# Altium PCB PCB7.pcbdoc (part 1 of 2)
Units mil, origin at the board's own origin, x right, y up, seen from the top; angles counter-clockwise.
Board outline 2240.69 x 1522.77 mil, 8 copper layers (Top Layer, Inner1, Inner2, Inner3, Inner4, Inner5, Inner6, Bottom Layer); 54 components, 78 nets, 968 pads, 282 vias.
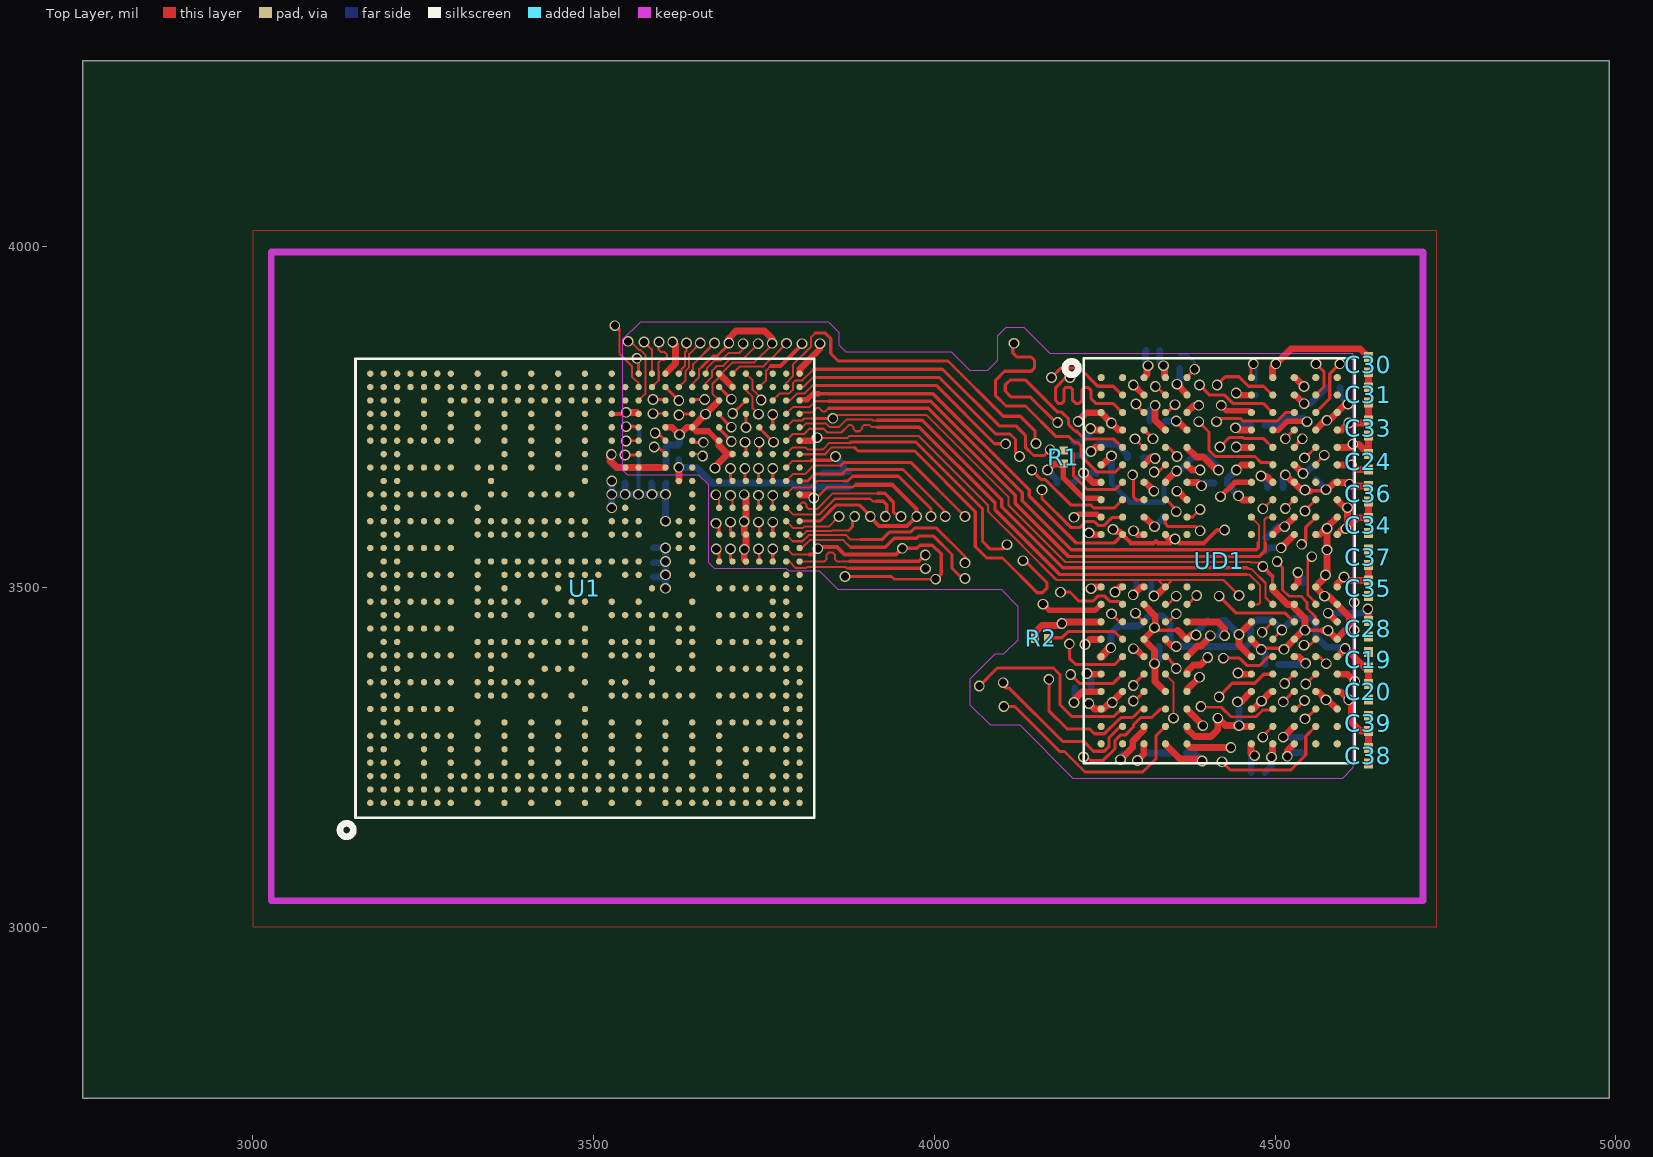
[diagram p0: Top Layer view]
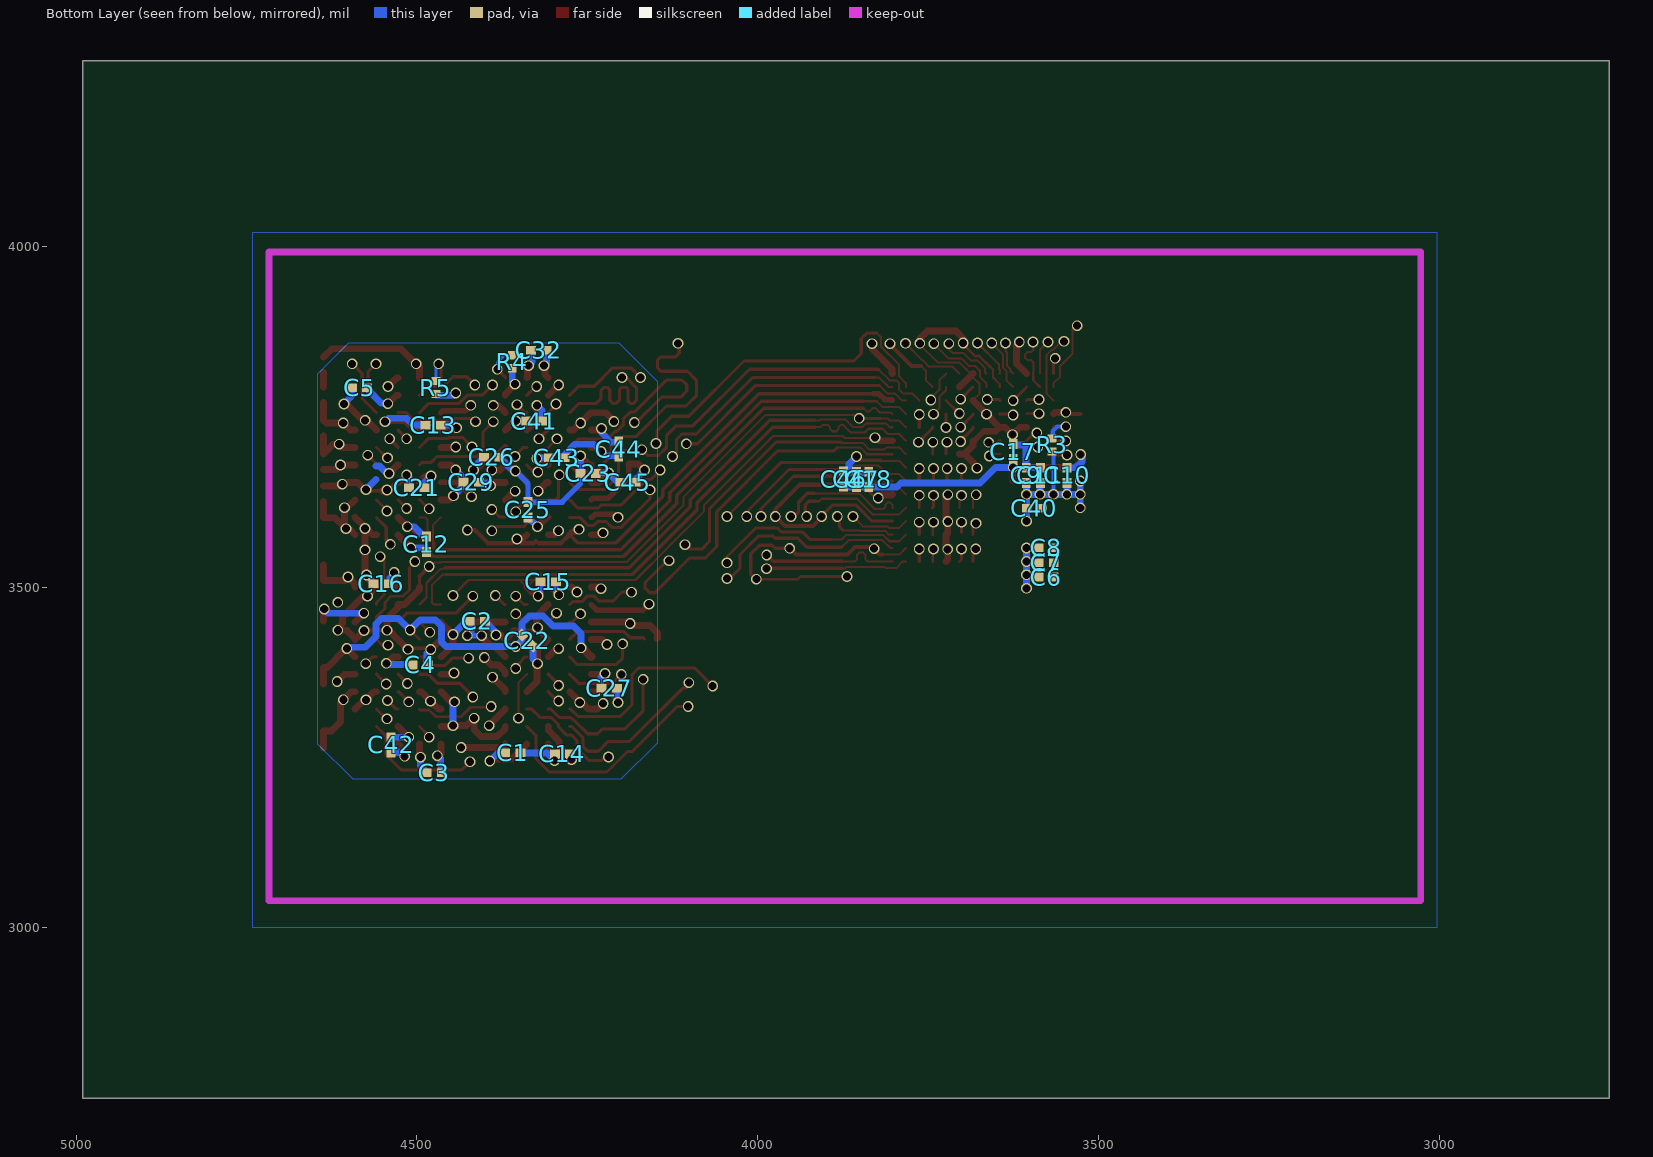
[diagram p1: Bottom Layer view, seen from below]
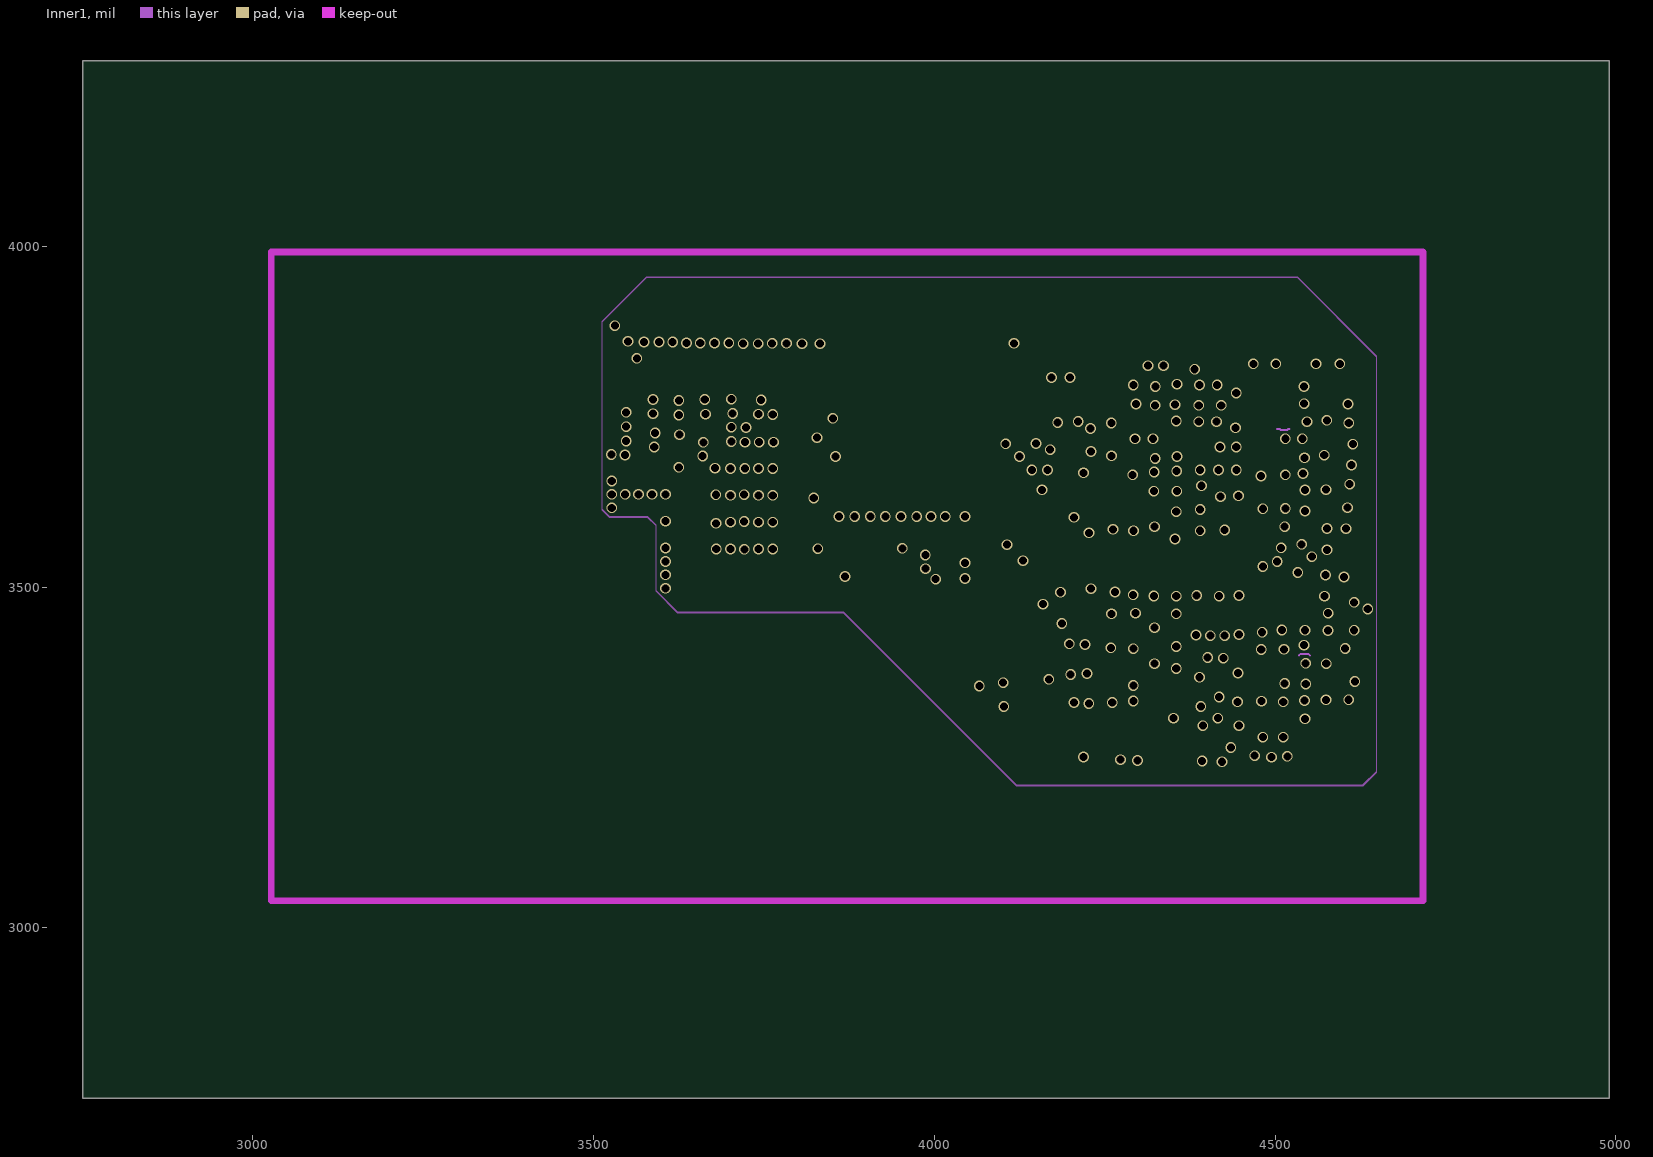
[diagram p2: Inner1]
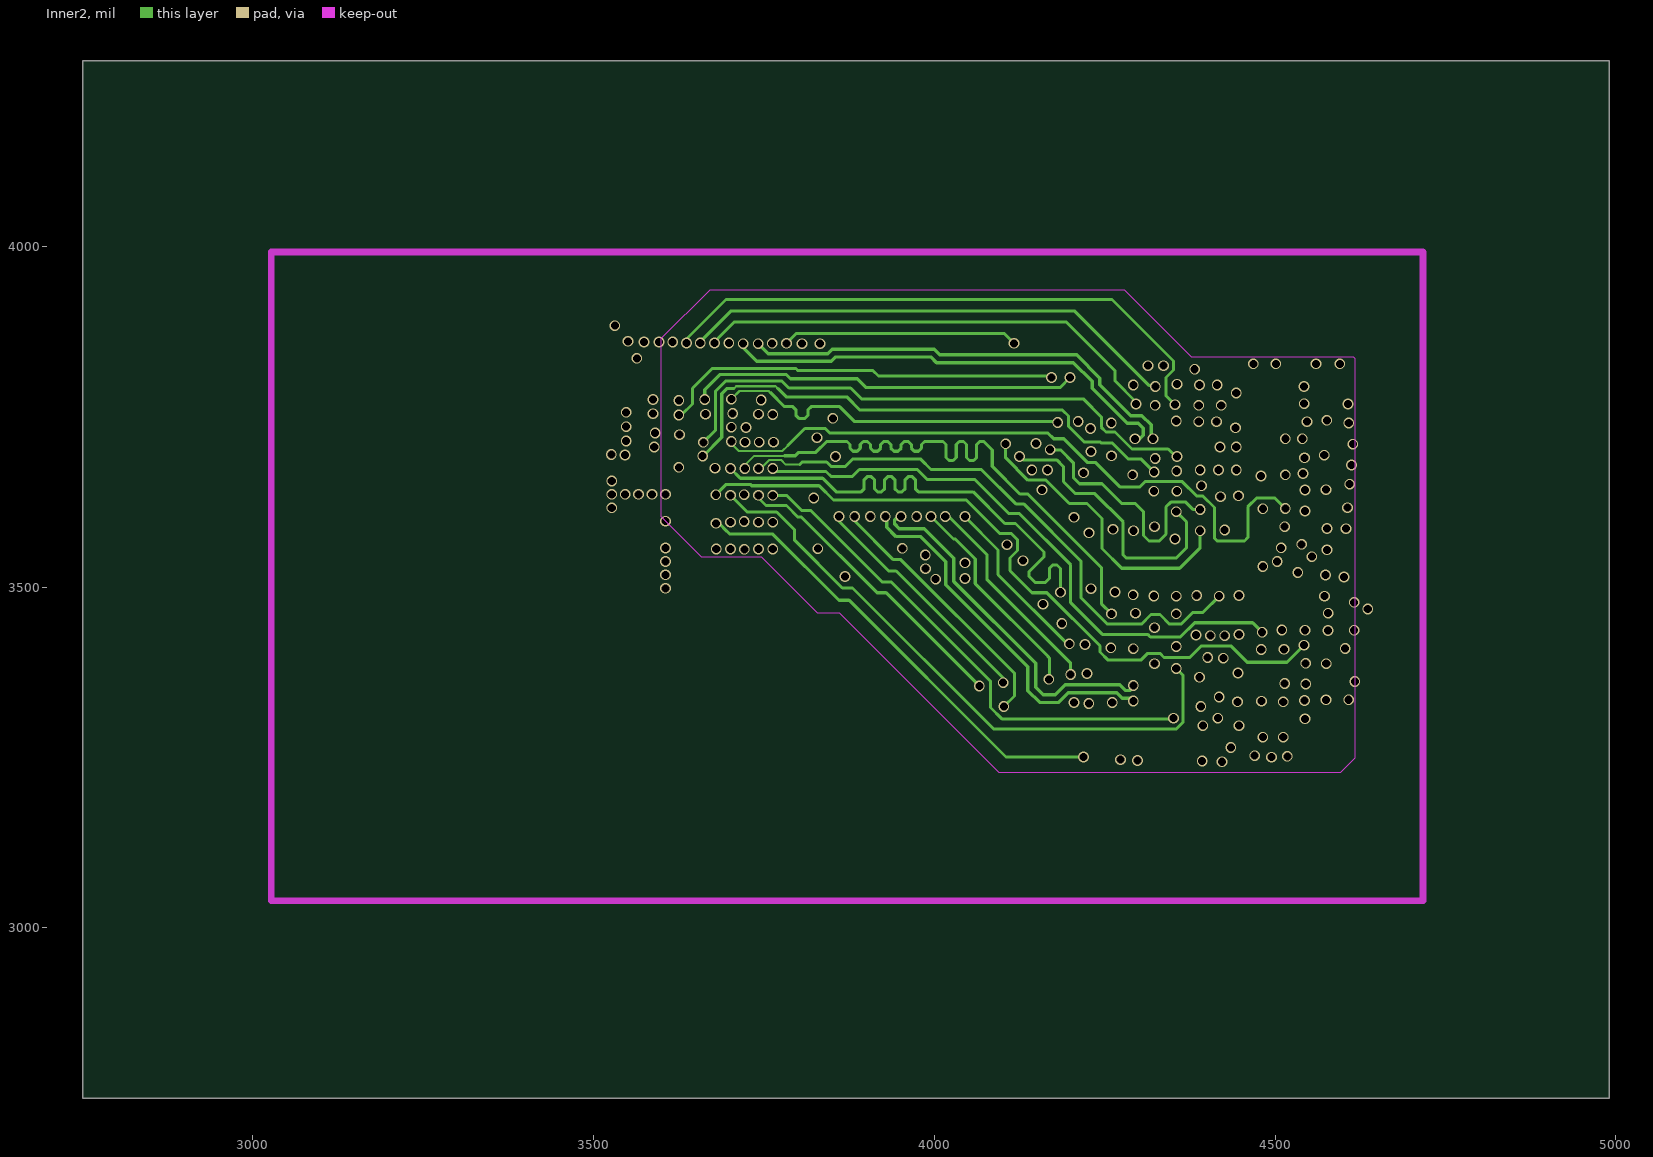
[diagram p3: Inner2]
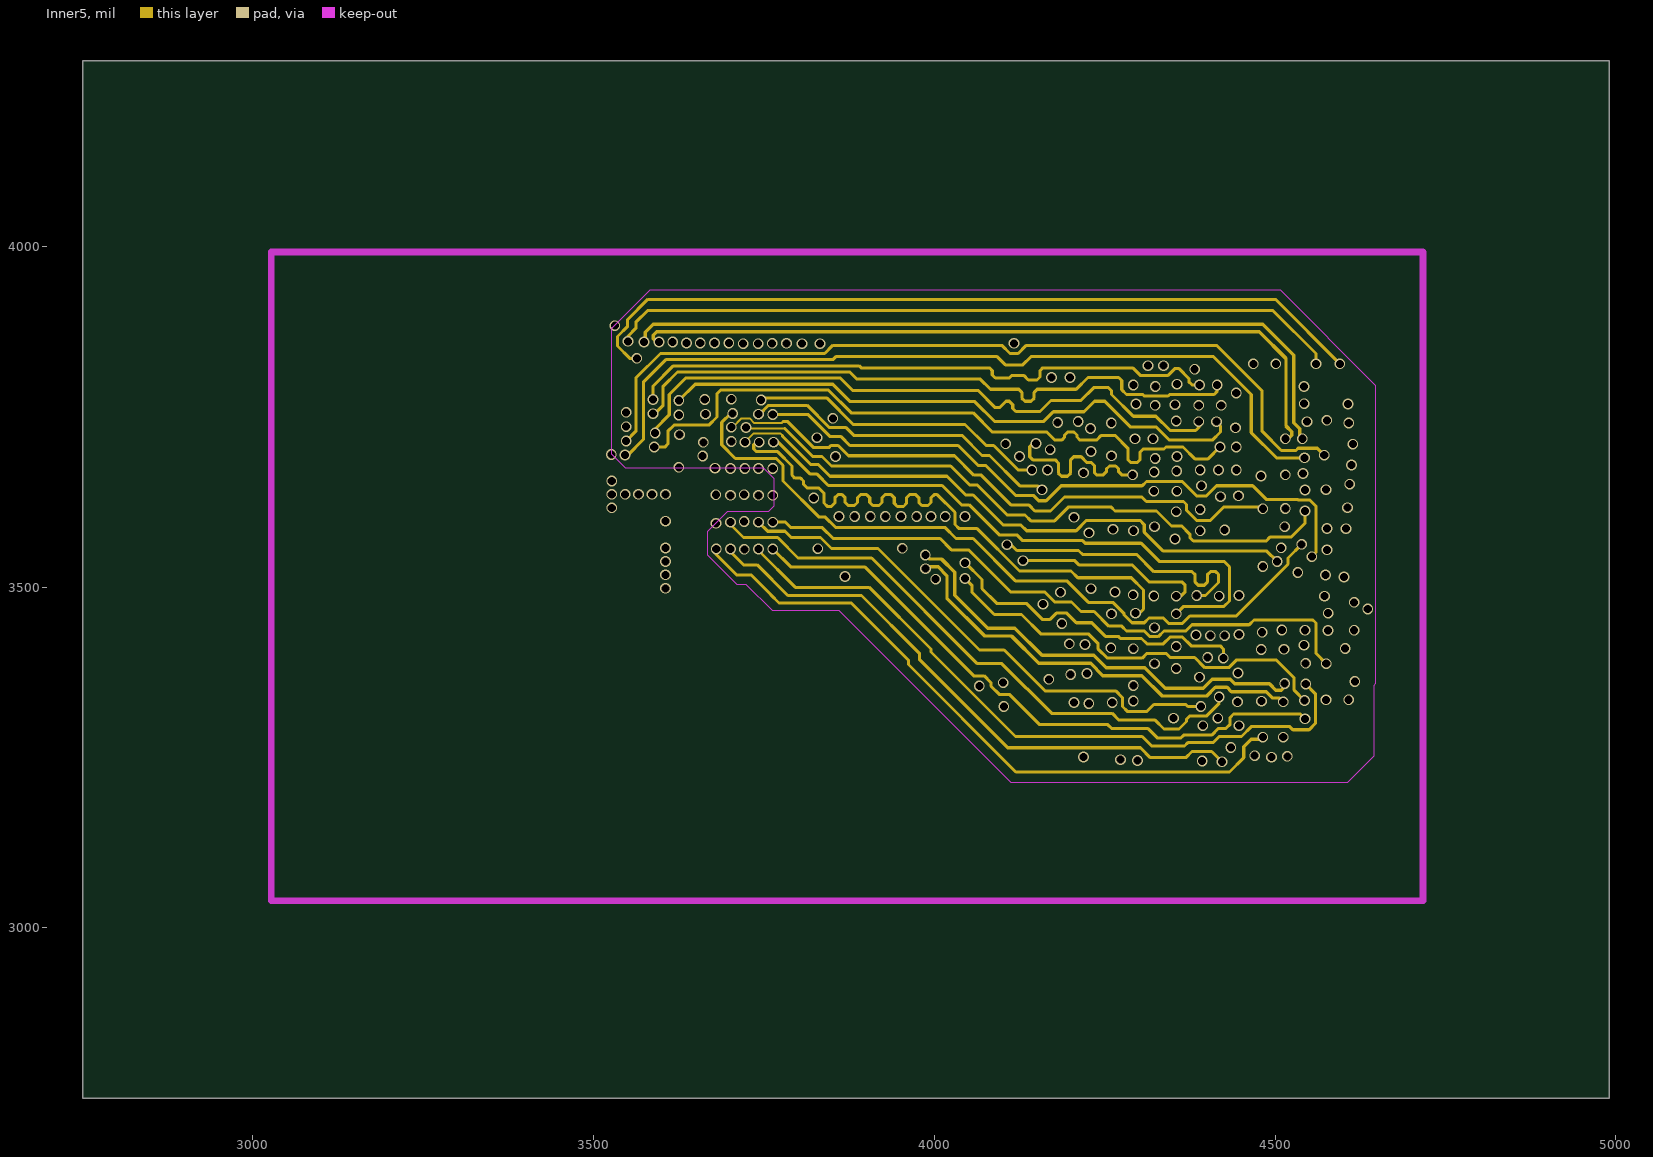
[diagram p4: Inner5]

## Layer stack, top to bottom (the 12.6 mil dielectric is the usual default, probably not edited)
Top Layer: signal copper (thickness not stored)
Dielectric: dielectric 12.6, FR-4, Dk 4.8
Inner1: signal copper (thickness not stored)
Dielectric: dielectric 12.6, FR-4, Dk 4.8
Inner2: signal copper (thickness not stored)
Dielectric: dielectric 12.6, FR-4, Dk 4.8
Inner3: signal copper (thickness not stored)
Dielectric: dielectric 12.6, FR-4, Dk 4.8
Inner4: signal copper (thickness not stored)
Dielectric: dielectric 12.6, FR-4, Dk 4.8
Inner5: signal copper (thickness not stored)
Dielectric: dielectric 12.6, FR-4, Dk 4.8
Inner6: signal copper (thickness not stored)
Dielectric: dielectric 12.6, FR-4, Dk 4.8
Bottom Layer: signal copper (thickness not stored)

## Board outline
4990.69,2750 2750,2750 2750,4272.77 4990.69,4272.77

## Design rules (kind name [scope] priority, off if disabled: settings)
Clearance safeClearance [All] p1: gap=7 ignorepadtopadclearanceinfootprint=FALSE except(3: Track-Track Track-SMDPad SMDPad-SMDPad Track-THPad SMDPad-THPad THPad-THPad Track-Via SMDPad-Via THPad-Via Via-Via Track-Hole SMDPad-Hole THPad-Hole Via-Hole; 3.5: Track-Fill SMDPad-Fill THPad-Fill Via-Fill Fill-Fill Track-Region SMDPad-Region THPad-Region Via-Region Fill-Region Region-Region Track-Poly SMDPad-Poly THPad-Poly Via-Poly Fill-Poly Region-Poly Poly-Poly Track-Text SMDPad-Text THPad-Text Via-Text Fill-Text Region-Text Poly-Text Text-Text SMDPad-Sheet THPad-Sheet Fill-Hole Region-Hole Poly-Hole Text-Hole Sheet-Hole; 11.8: Track-Sheet Via-Sheet Fill-Sheet Region-Sheet Poly-Sheet Text-Sheet)
DiffPairsRouting differentialPair [All] p1: maxuncoupledlength=50 minlimit=0 maxlimit=4.0157 mostfreqgap=4.0157 toplayer_minwidth=4.0157 toplayer_prefwidth=10 toplayer_maxwidth=100 bottomlayer_minwidth=4.0157 bottomlayer_prefwidth=10 bottomlayer_maxwidth=100 midlayer1_minwidth=4.0157 midlayer1_prefwidth=10 midlayer1_maxwidth=100 midlayer2_minwidth=4.0157 midlayer2_prefwidth=10 midlayer2_maxwidth=100 midlayer3_minwidth=4.0157 midlayer3_prefwidth=10 midlayer3_maxwidth=100 midlayer4_minwidth=4.0157 midlayer4_prefwidth=10 midlayer4_maxwidth=100 midlayer5_minwidth=4.0157 midlayer5_prefwidth=10 midlayer5_maxwidth=100 midlayer6_minwidth=4.0157 midlayer6_prefwidth=10 midlayer6_maxwidth=100
PasteMaskExpansion pasteMaskExpansion [All] p1: expansion=0
PlaneConnect innerPlane [All] p1: planeconnectstyle=Relief reliefexpansion=20 reliefentries=4 reliefconductorwidth=10 reliefairgap=10
PolygonConnect copperRegion [All] p1: connectstyle=Relief reliefentries=4 reliefconductorwidth=10 polygonreliefangle="90 Angle" airgapwidth=10
PolygonConnect TBCopper [All] p1: connectstyle=Relief reliefentries=4 reliefconductorwidth=5.9843 polygonreliefangle="90 Angle" airgapwidth=5.9843
PolygonConnect DRAMCopper [All] p1: connectstyle=Relief reliefentries=4 reliefconductorwidth=4.0157 polygonreliefangle="90 Angle" airgapwidth=4.0157
RoutingVias viaSize [All] p1: viastyle="Through Hole" holewidth=7.9134 minholewidth=7.9134 maxholewidth=236.1812 width=17.7166 minwidth=15.748 maxwidth=393.7008
SolderMaskExpansion solderMaskExpansion [All] p1: useseparateexpansions=TRUE expansion=4.0157 expansionbottom=4.0157
Width trackWidth [All] p1: maxlimit=100 minlimit=3 preferedwidth=4

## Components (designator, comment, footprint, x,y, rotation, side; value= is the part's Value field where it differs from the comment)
C1 "0201X225M6R3NT" "c0201 nsk" 4359,3256.77 r180 bottom
C2 "0201X225M6R3NT" "c0201 nsk" 4411,3449.77 r180 bottom
C3 "GRM033R61A104KE15D" "c0201 nsk" 4475,3227.77 r0 bottom
C4 "GRM033R61A104KE15D" "c0201 nsk" 4495.5,3385.77 r0 bottom
C5 "GRM033R61A104KE15D" "c0201 nsk" 4584,3792.77 r180 bottom
C6 "GRM033R61A104KE15D" "c0201 nsk" 3577,3514.77 r0 bottom
C7 "GRM033R61A104KE15D" "c0201 nsk" 3577,3535.77 r0 bottom
C8 "GRM033R61A104KE15D" "c0201 nsk" 3577,3557.77 r0 bottom
C9 "GRM033R61A104KE15D" "c0201 nsk" 3606,3663.77 r270 bottom
C10 "GRM033R61A104KE15D" "c0201 nsk" 3546,3663.77 r270 bottom
C11 "GRM033R61A104KE15D" "c0201 nsk" 3585,3663.77 r270 bottom
C12 "GRM033R61A104KE15D" "c0201 nsk" 4486,3562.77 r270 bottom
C13 "GRM033R61A104KE15D" "c0201 nsk" 4476,3737.77 r180 bottom
C14 "GRM033R61A104KE15D" "c0201 nsk" 4286.13,3255.54 r180 bottom
C15 "GRM033R61A104KE15D" "c0201 nsk" 4307,3507.77 r180 bottom
C16 "GRM033R61A104KE15D" "c0201 nsk" 4552,3504.77 r180 bottom
C17 "0201X225M6R3NT" "c0201 nsk" 3625,3699.27 r90 bottom
C18 "GRM033R61A104KE15D" "c0201 nsk" 3837,3657.77 r270 bottom
C19 "0201X225M6R3NT" "c0201 nsk" 4637,3393.77 r90 top
C20 "GRM033R61A104KE15D" "c0201 nsk" 4637,3346.77 r90 top
C21 "GRM033R61A104KE15D" "c0201 nsk" 4500,3645.77 r180 bottom
C22 "GRM033R61A104KE15D" "c0201 nsk" 4338,3421.77 r45 bottom
C23 "GRM033R61A104KE15D" "c0201 nsk" 4249,3666.77 r0 bottom
C24 "GRM033R61A104KE15D" "c0201 nsk" 4637,3683.77 r270 top
C25 "GRM033R61A104KE15D" "c0201 nsk" 4337,3613.77 r90 bottom
C26 "GRM033R61A104KE15D" "c0201 nsk" 4390,3690.77 r180 bottom
C27 "0201X225M6R3NT" "c0201 nsk" 4218,3351.77 r0 bottom
C28 "0201X225M6R3NT" "c0201 nsk" 4637,3438.77 r270 top
C29 "GRM033R61A104KE15D" "c0201 nsk" 4420.5,3653.77 r0 bottom
C30 "GRM033R61A104KE15D" "c0201 nsk" 4637,3826.77 r90 top
C31 "GRM033R61A104KE15D" "c0201 nsk" 4637,3781.77 r270 top
C32 "0201X225M6R3NT" "c0201 nsk" 4321,3847.77 r180 bottom
C33 "GRM033R61A104KE15D" "c0201 nsk" 4637,3733.77 r90 top
C34 "GRM033R61A104KE15D" "c0201 nsk" 4637,3590.77 r90 top
C35 "GRM033R61A104KE15D" "c0201 nsk" 4637,3498.77 r90 top
C36 "GRM033R61A104KE15D" "c0201 nsk" 4637,3636.77 r270 top
C37 "GRM033R61A104KE15D" "c0201 nsk" 4637,3543.77 r270 top
C38 "GRM033R61A104KE15D" "c0201 nsk" 4637,3252.77 r90 top
C39 "GRM033R61A104KE15D" "c0201 nsk" 4637,3299.77 r270 top
C40 "GRM033R61A104KE15D" "c0201 nsk" 3594,3615.77 r0 bottom
C41 "GRM033R61A104KE15D" "c0201 nsk" 4328,3743.77 r0 bottom
C42 "GRM033R61A104KE15D" "c0201 nsk" 4538,3268.77 r90 bottom
C43 "GRM033R61A104KE15D" "c0201 nsk" 4295,3689.77 r0 bottom
C44 "GRM033R61A104KE15D" "c0201 nsk" 4204,3702.77 r90 bottom
C45 "GRM033R61A104KE15D" "c0201 nsk" 4190,3653.77 r180 bottom
C46 "0201X225M6R3NT" "c0201 nsk" 3874,3658.77 r90 bottom
C47 "GRM033R61A104KE15D" "c0201 nsk" 3855,3657.77 r270 bottom
R1 "Res_0201" "r0201 nsk" 4190,3690.77 r270 top
R2 "Res_0201" "r0201 nsk" 4157,3424.77 r180 top
R3 "Res_0201" "r0201 nsk" 3568,3708.77 r270 bottom
R4 "Res_0201" "r0201 nsk" 4360,3830.77 r270 bottom
R5 "Res_0201" "r0201 nsk" 4472,3792.77 r270 bottom
U1 "T527" T527-BGA664 3487.26,3498.32 r90 top
UD1 "LPDDR4_FBGA200" BGA200P65_80B1000_1500H90 4418,3538.77 r0 top

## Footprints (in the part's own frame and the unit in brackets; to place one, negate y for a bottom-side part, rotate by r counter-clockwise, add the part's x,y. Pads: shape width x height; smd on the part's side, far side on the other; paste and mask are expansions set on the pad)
BGA200P65_80B1000_1500H90 [mm]
  round 0.27 smd: A1(-4.4,6.825) A2(-3.6,6.825) A3(-2.8,6.825) A4(-2,6.825) A5(-1.2,6.825) A8(1.2,6.825) A9(2,6.825) A10(2.8,6.825) A11(3.6,6.825) A12(4.4,6.825) AA1(-4.4,-6.175) AA2(-3.6,-6.175) AA3(-2.8,-6.175) AA4(-2,-6.175) AA5(-1.2,-6.175) AA8(1.2,-6.175) AA9(2,-6.175) AA10(2.8,-6.175) AA11(3.6,-6.175) AA12(4.4,-6.175) AB1(-4.4,-6.825) AB2(-3.6,-6.825) AB3(-2.8,-6.825) AB4(-2,-6.825) AB5(-1.2,-6.825) AB8(1.2,-6.825) AB9(2,-6.825) AB10(2.8,-6.825) AB11(3.6,-6.825) AB12(4.4,-6.825) B1(-4.4,6.175) B2(-3.6,6.175) B3(-2.8,6.175) B4(-2,6.175) B5(-1.2,6.175) B8(1.2,6.175) B9(2,6.175) B10(2.8,6.175) B11(3.6,6.175) B12(4.4,6.175) C1(-4.4,5.525) C2(-3.6,5.525) C3(-2.8,5.525) C4(-2,5.525) C5(-1.2,5.525) C8(1.2,5.525) C9(2,5.525) C10(2.8,5.525) C11(3.6,5.525) C12(4.4,5.525) D1(-4.4,4.875) D2(-3.6,4.875) D3(-2.8,4.875) D4(-2,4.875) D5(-1.2,4.875) D8(1.2,4.875) D9(2,4.875) D10(2.8,4.875) D11(3.6,4.875) D12(4.4,4.875) E1(-4.4,4.225) E2(-3.6,4.225) E3(-2.8,4.225) E4(-2,4.225) E5(-1.2,4.225) E8(1.2,4.225) E9(2,4.225) E10(2.8,4.225) E11(3.6,4.225) E12(4.4,4.225) F1(-4.4,3.575) F2(-3.6,3.575) F3(-2.8,3.575) F4(-2,3.575) F5(-1.2,3.575) F8(1.2,3.575) F9(2,3.575) F10(2.8,3.575) F11(3.6,3.575) F12(4.4,3.575) G1(-4.4,2.925) G2(-3.6,2.925) G3(-2.8,2.925) G4(-2,2.925) G5(-1.2,2.925) G8(1.2,2.925) G9(2,2.925) G10(2.8,2.925) G11(3.6,2.925) G12(4.4,2.925) H1(-4.4,2.275) H2(-3.6,2.275) H3(-2.8,2.275) H4(-2,2.275) H5(-1.2,2.275) H8(1.2,2.275) H9(2,2.275) H10(2.8,2.275) H11(3.6,2.275) H12(4.4,2.275) J1(-4.4,1.625) J2(-3.6,1.625) J3(-2.8,1.625) J4(-2,1.625) J5(-1.2,1.625) J8(1.2,1.625) J9(2,1.625) J10(2.8,1.625) J11(3.6,1.625) J12(4.4,1.625) K1(-4.4,0.975) K2(-3.6,0.975) K3(-2.8,0.975) K4(-2,0.975) K5(-1.2,0.975) K8(1.2,0.975) K9(2,0.975) K10(2.8,0.975) K11(3.6,0.975) K12(4.4,0.975) N1(-4.4,-0.975) N2(-3.6,-0.975) N3(-2.8,-0.975) N4(-2,-0.975) N5(-1.2,-0.975) N8(1.2,-0.975) N9(2,-0.975) N10(2.8,-0.975) N11(3.6,-0.975) N12(4.4,-0.975) P1(-4.4,-1.625) P2(-3.6,-1.625) P3(-2.8,-1.625) P4(-2,-1.625) P5(-1.2,-1.625) P8(1.2,-1.625) P9(2,-1.625) P10(2.8,-1.625) P11(3.6,-1.625) P12(4.4,-1.625) R1(-4.4,-2.275) R2(-3.6,-2.275) R3(-2.8,-2.275) R4(-2,-2.275) R5(-1.2,-2.275) R8(1.2,-2.275) R9(2,-2.275) R10(2.8,-2.275) R11(3.6,-2.275) R12(4.4,-2.275) T1(-4.4,-2.925) T2(-3.6,-2.925) T3(-2.8,-2.925) T4(-2,-2.925) T5(-1.2,-2.925) T8(1.2,-2.925) T9(2,-2.925) T10(2.8,-2.925) T11(3.6,-2.925) T12(4.4,-2.925) U1(-4.4,-3.575) U2(-3.6,-3.575) U3(-2.8,-3.575) U4(-2,-3.575) U5(-1.2,-3.575) U8(1.2,-3.575) U9(2,-3.575) U10(2.8,-3.575) U11(3.6,-3.575) U12(4.4,-3.575) V1(-4.4,-4.225) V2(-3.6,-4.225) V3(-2.8,-4.225) V4(-2,-4.225) V5(-1.2,-4.225) V8(1.2,-4.225) V9(2,-4.225) V10(2.8,-4.225) V11(3.6,-4.225) V12(4.4,-4.225) W1(-4.4,-4.875) W2(-3.6,-4.875) W3(-2.8,-4.875) W4(-2,-4.875) W5(-1.2,-4.875) W8(1.2,-4.875) W9(2,-4.875) W10(2.8,-4.875) W11(3.6,-4.875) W12(4.4,-4.875) Y1(-4.4,-5.525) Y2(-3.6,-5.525) Y3(-2.8,-5.525) Y4(-2,-5.525) Y5(-1.2,-5.525) Y8(1.2,-5.525) Y9(2,-5.525) Y10(2.8,-5.525) Y11(3.6,-5.525) Y12(4.4,-5.525)
  silkscreen extent -5.75,-7.55 5.05,7.55
"c0201 nsk" [mil]
  rect 14.51x12.76 smd: 1(-11.5,0) 2(11,0)
"r0201 nsk" [mil]
  rect 11.93x12.76 smd: 1(-9.51,0) 2(9.51,0)
T527-BGA664 [mm]
  round 0.239 smd: A1(-8,8) A2(-7.5,8) A3(-7,8) A4(-6.5,8) A5(-6,8) A6(-5.5,8) A8(-4.5,8) A10(-3.5,8) A12(-2.5,8) A14(-1.5,8) A16(-0.5,8) A18(0.5,8) A20(1.5,8) A22(2.5,8) A24(3.5,8) A26(4.5,8) A28(5.5,8) A29(6,8) A30(6.5,8) A31(7,8) A32(7.5,8) A33(8,8) AA1(-8,-2) AA2(-7.5,-2) AA3(-7,-2) AA4(-6.5,-2) AA5(-6,-2) AA6(-5.5,-2) AA7(-5,-2) AA9(-4,-2) AA12(-2.5,-2) AA13(-2,-2) AA15(-1,-2) AA16(-0.5,-2) AA18(0.5,-2) AA19(1,-2) AA21(2,-2) AA22(2.5,-2) AA24(3.5,-2) AA26(4.5,-2) AA27(5,-2) AA28(5.5,-2) AA29(6,-2) AA30(6.5,-2) AA31(7,-2) AA32(7.5,-2) AA33(8,-2) AB2(-7.5,-2.5) AB3(-7,-2.5) AB9(-4,-2.5) AB10(-3.5,-2.5) AB11(-3,-2.5) AB12(-2.5,-2.5) AB13(-2,-2.5) AB14(-1.5,-2.5) AB15(-1,-2.5) AB17(0,-2.5) AB24(3.5,-2.5) AB32(7.5,-2.5) AB33(8,-2.5) AC1(-8,-3) AC2(-7.5,-3) AC3(-7,-3) AC4(-6.5,-3) AC5(-6,-3) AC6(-5.5,-3) AC7(-5,-3) AC9(-4,-3) AC15(-1,-3) AC17(0,-3) AC18(0.5,-3) AC19(1,-3) AC20(1.5,-3) AC22(2.5,-3) AC24(3.5,-3) AC26(4.5,-3) AC27(5,-3) AC28(5.5,-3) AC29(6,-3) AC30(6.5,-3) AC31(7,-3) AC32(7.5,-3) AC33(8,-3) AD1(-8,-3.5) AD2(-7.5,-3.5) AD9(-4,-3.5) AD11(-3,-3.5) AD13(-2,-3.5) AD14(-1.5,-3.5) AD15(-1,-3.5) AD20(1.5,-3.5) AD21(2,-3.5) AD22(2.5,-3.5) AD25(4,-3.5) AD32(7.5,-3.5) AD33(8,-3.5) AE1(-8,-4) AE2(-7.5,-4) AE3(-7,-4) AE4(-6.5,-4) AE5(-6,-4) AE6(-5.5,-4) AE7(-5,-4) AE9(-4,-4) AE11(-3,-4) AE12(-2.5,-4) AE13(-2,-4) AE14(-1.5,-4) AE16(-0.5,-4) AE18(0.5,-4) AE19(1,-4) AE20(1.5,-4) AE21(2,-4) AE22(2.5,-4) AE23(3,-4) AE24(3.5,-4) AE25(4,-4) AE26(4.5,-4) AE27(5,-4) AE28(5.5,-4) AE29(6,-4) AE30(6.5,-4) AE31(7,-4) AE32(7.5,-4) AE33(8,-4) AF1(-8,-4.5) AF2(-7.5,-4.5) AF32(7.5,-4.5) AF33(8,-4.5) AG1(-8,-5) AG2(-7.5,-5) AG3(-7,-5) AG4(-6.5,-5) AG5(-6,-5) AG6(-5.5,-5) AG7(-5,-5) AG9(-4,-5) AG11(-3,-5) AG13(-2,-5) AG15(-1,-5) AG17(0,-5) AG19(1,-5) AG21(2,-5) AG23(3,-5) AG25(4,-5) AG28(5.5,-5) AG29(6,-5) AG30(6.5,-5) AG31(7,-5) AG32(7.5,-5) AG33(8,-5) AH1(-8,-5.5) AH2(-7.5,-5.5) AH7(-5,-5.5) AH9(-4,-5.5) AH11(-3,-5.5) AH13(-2,-5.5) AH15(-1,-5.5) AH17(0,-5.5) AH19(1,-5.5) AH21(2,-5.5) AH23(3,-5.5) AH25(4,-5.5) AH27(5,-5.5) AH32(7.5,-5.5) AH33(8,-5.5) AJ1(-8,-6) AJ2(-7.5,-6) AJ3(-7,-6) AJ4(-6.5,-6) AJ5(-6,-6) AJ7(-5,-6) AJ9(-4,-6) AJ11(-3,-6) AJ13(-2,-6) AJ15(-1,-6) AJ17(0,-6) AJ19(1,-6) AJ21(2,-6) AJ23(3,-6) AJ25(4,-6) AJ27(5,-6) AJ30(6.5,-6) AJ31(7,-6) AJ32(7.5,-6) AJ33(8,-6) AK1(-8,-6.5) AK2(-7.5,-6.5) AK5(-6,-6.5) AK7(-5,-6.5) AK9(-4,-6.5) AK11(-3,-6.5) AK13(-2,-6.5) AK15(-1,-6.5) AK17(0,-6.5) AK19(1,-6.5) AK21(2,-6.5) AK23(3,-6.5) AK25(4,-6.5) AK27(5,-6.5) AK29(6,-6.5) AK32(7.5,-6.5) AK33(8,-6.5) AL1(-8,-7) AL2(-7.5,-7) AL3(-7,-7) AL5(-6,-7) AL7(-5,-7) AL9(-4,-7) AL11(-3,-7) AL12(-2.5,-7) AL13(-2,-7) AL14(-1.5,-7) AL15(-1,-7) AL16(-0.5,-7) AL17(0,-7) AL19(1,-7) AL21(2,-7) AL23(3,-7) AL25(4,-7) AL27(5,-7) AL29(6,-7) AL31(7,-7) AL32(7.5,-7) AL33(8,-7) AM1(-8,-7.5) AM2(-7.5,-7.5) AM3(-7,-7.5) AM4(-6.5,-7.5) AM5(-6,-7.5) AM6(-5.5,-7.5) AM7(-5,-7.5) AM8(-4.5,-7.5) AM9(-4,-7.5) AM10(-3.5,-7.5) AM11(-3,-7.5) AM12(-2.5,-7.5) AM13(-2,-7.5) AM14(-1.5,-7.5) AM15(-1,-7.5) AM16(-0.5,-7.5) AM17(0,-7.5) AM18(0.5,-7.5) AM19(1,-7.5) AM20(1.5,-7.5) AM21(2,-7.5) AM22(2.5,-7.5) AM23(3,-7.5) AM24(3.5,-7.5) AM25(4,-7.5) AM26(4.5,-7.5) AM27(5,-7.5) AM28(5.5,-7.5) AM29(6,-7.5) AM30(6.5,-7.5) AM31(7,-7.5) AM32(7.5,-7.5) AM33(8,-7.5) AN1(-8,-8) AN2(-7.5,-8) AN3(-7,-8) AN4(-6.5,-8) AN5(-6,-8) AN6(-5.5,-8) AN7(-5,-8) AN8(-4.5,-8) AN9(-4,-8) AN10(-3.5,-8) AN11(-3,-8) AN13(-2,-8) AN15(-1,-8) AN17(0,-8) AN18(0.5,-8) AN19(1,-8) AN20(1.5,-8) AN21(2,-8) AN22(2.5,-8) AN23(3,-8) AN24(3.5,-8) AN25(4,-8) AN26(4.5,-8) AN27(5,-8) AN28(5.5,-8) AN29(6,-8) AN30(6.5,-8) AN31(7,-8) AN32(7.5,-8) AN33(8,-8) B1(-8,7.5) B2(-7.5,7.5) B3(-7,7.5) B4(-6.5,7.5) B5(-6,7.5) B6(-5.5,7.5) B7(-5,7.5) B8(-4.5,7.5) B9(-4,7.5) B10(-3.5,7.5) B11(-3,7.5) B12(-2.5,7.5) B13(-2,7.5) B14(-1.5,7.5) B15(-1,7.5) B16(-0.5,7.5) B17(0,7.5) B18(0.5,7.5) B19(1,7.5) B20(1.5,7.5) B21(2,7.5) B22(2.5,7.5) B23(3,7.5) B24(3.5,7.5) B25(4,7.5) B26(4.5,7.5) B27(5,7.5) B28(5.5,7.5) B29(6,7.5) B30(6.5,7.5) B31(7,7.5) B32(7.5,7.5) B33(8,7.5) C1(-8,7) C2(-7.5,7) C3(-7,7) C4(-6.5,7) C6(-5.5,7) C7(-5,7) C8(-4.5,7) C9(-4,7) C10(-3.5,7) C11(-3,7) C12(-2.5,7) C13(-2,7) C14(-1.5,7) C15(-1,7) C16(-0.5,7) C17(0,7) C18(0.5,7) C19(1,7) C20(1.5,7) C21(2,7) C22(2.5,7) C23(3,7) C24(3.5,7) C25(4,7) C26(4.5,7) C27(5,7) C28(5.5,7) C29(6,7) C30(6.5,7) C31(7,7) C32(7.5,7) C33(8,7) D1(-8,6.5) D2(-7.5,6.5) D6(-5.5,6.5) D8(-4.5,6.5) D10(-3.5,6.5) D12(-2.5,6.5) D14(-1.5,6.5) D16(-0.5,6.5) D18(0.5,6.5) D20(1.5,6.5) D22(2.5,6.5) D24(3.5,6.5) D26(4.5,6.5) D28(5.5,6.5) D32(7.5,6.5) D33(8,6.5) E1(-8,6) E2(-7.5,6) E3(-7,6) E4(-6.5,6) E5(-6,6) E6(-5.5,6) E8(-4.5,6) E10(-3.5,6) E12(-2.5,6) E14(-1.5,6) E16(-0.5,6) E18(0.5,6) E20(1.5,6) E22(2.5,6) E24(3.5,6) E26(4.5,6) E28(5.5,6) E29(6,6) E30(6.5,6) E31(7,6) E32(7.5,6) E33(8,6) F1(-8,5.5) F2(-7.5,5.5) F6(-5.5,5.5) F8(-4.5,5.5) F10(-3.5,5.5) F12(-2.5,5.5) F14(-1.5,5.5) F16(-0.5,5.5) F18(0.5,5.5) F20(1.5,5.5) F22(2.5,5.5) F24(3.5,5.5) F26(4.5,5.5) F28(5.5,5.5) F32(7.5,5.5) F33(8,5.5) G1(-8,5) G2(-7.5,5) G3(-7,5) G4(-6.5,5) G5(-6,5) G6(-5.5,5) G8(-4.5,5) G10(-3.5,5) G12(-2.5,5) G14(-1.5,5) G16(-0.5,5) G18(0.5,5) G20(1.5,5) G22(2.5,5) G24(3.5,5) G26(4.5,5) G28(5.5,5) G29(6,5) G30(6.5,5) G31(7,5) G32(7.5,5) G33(8,5) H2(-7.5,4.5) H3(-7,4.5) H24(3.5,4.5) H31(7,4.5) H32(7.5,4.5) J1(-8,4) J2(-7.5,4) J3(-7,4) J4(-6.5,4) J5(-6,4) J6(-5.5,4) J7(-5,4) J9(-4,4) J10(-3.5,4) J12(-2.5,4) J13(-2,4) J15(-1,4) J16(-0.5,4) J17(0,4) J18(0.5,4) J19(1,4) J21(2,4) J22(2.5,4) J23(3,4) J26(4.5,4) J28(5.5,4) J29(6,4) J30(6.5,4) J31(7,4) J32(7.5,4) J33(8,4) K2(-7.5,3.5) K3(-7,3.5) K9(-4,3.5) K10(-3.5,3.5) K11(-3,3.5) K12(-2.5,3.5) K13(-2,3.5) K15(-1,3.5) K16(-0.5,3.5) K19(1,3.5) K21(2,3.5) K22(2.5,3.5) K24(3.5,3.5) K25(4,3.5) K26(4.5,3.5) K31(7,3.5) K32(7.5,3.5) L1(-8,3) L2(-7.5,3) L3(-7,3) L4(-6.5,3) L5(-6,3) L6(-5.5,3) L7(-5,3) L9(-4,3) L10(-3.5,3) L12(-2.5,3) L13(-2,3) L15(-1,3) L16(-0.5,3) L17(0,3) L18(0.5,3) L19(1,3) L21(2,3) L22(2.5,3) L24(3.5,3) L26(4.5,3) L27(5,3) L28(5.5,3) L29(6,3) L30(6.5,3) L31(7,3) L32(7.5,3) L33(8,3) M2(-7.5,2.5) M3(-7,2.5) M10(-3.5,2.5) M13(-2,2.5) M16(-0.5,2.5) M18(0.5,2.5) M19(1,2.5) M21(2,2.5) M22(2.5,2.5) M31(7,2.5) M32(7.5,2.5) N1(-8,2) N2(-7.5,2) N3(-7,2) N4(-6.5,2) N5(-6,2) N6(-5.5,2) N7(-5,2) N9(-4,2) N10(-3.5,2) N12(-2.5,2) N13(-2,2) N15(-1,2) N18(0.5,2) N19(1,2) N21(2,2) N22(2.5,2) N24(3.5,2) N26(4.5,2) N27(5,2) N28(5.5,2) N29(6,2) N30(6.5,2) N31(7,2) N32(7.5,2) N33(8,2) P2(-7.5,1.5) P3(-7,1.5) P9(-4,1.5) P11(-3,1.5) P13(-2,1.5) P16(-0.5,1.5) P18(0.5,1.5) P19(1,1.5) P21(2,1.5) P22(2.5,1.5) P24(3.5,1.5) P31(7,1.5) P32(7.5,1.5) R1(-8,1) R2(-7.5,1) R3(-7,1) R4(-6.5,1) R5(-6,1) R6(-5.5,1) R7(-5,1) R11(-3,1) R13(-2,1) R15(-1,1) R17(0,1) R18(0.5,1) R19(1,1) R22(2.5,1) R24(3.5,1) R26(4.5,1) R27(5,1) R28(5.5,1) R29(6,1) R30(6.5,1) R31(7,1) R32(7.5,1) R33(8,1) T2(-7.5,0.5) T3(-7,0.5) T9(-4,0.5) T11(-3,0.5) T13(-2,0.5) T15(-1,0.5) T16(-0.5,0.5) T18(0.5,0.5) T19(1,0.5) T21(2,0.5) T22(2.5,0.5) T24(3.5,0.5) T31(7,0.5) T32(7.5,0.5) U1(-8,0) U2(-7.5,0) U3(-7,0) U4(-6.5,0) U5(-6,0) U6(-5.5,0) U7(-5,0) U8(-4.5,0) U10(-3.5,0) U12(-2.5,0) U13(-2,0) U14(-1.5,0) U16(-0.5,0) U18(0.5,0) U19(1,0) U21(2,0) U22(2.5,0) U25(4,0) U26(4.5,0) U27(5,0) U28(5.5,0) U29(6,0) U30(6.5,0) U31(7,0) U32(7.5,0) U33(8,0) V2(-7.5,-0.5) V3(-7,-0.5) V18(0.5,-0.5) V19(1,-0.5) V31(7,-0.5) V32(7.5,-0.5) W1(-8,-1) W2(-7.5,-1) W3(-7,-1) W4(-6.5,-1) W5(-6,-1) W6(-5.5,-1) W7(-5,-1) W9(-4,-1) W10(-3.5,-1) W12(-2.5,-1) W13(-2,-1) W15(-1,-1) W16(-0.5,-1) W19(1,-1) W21(2,-1) W22(2.5,-1) W23(3,-1) W24(3.5,-1) W25(4,-1) W27(5,-1) W28(5.5,-1) W29(6,-1) W30(6.5,-1) W31(7,-1) W32(7.5,-1) W33(8,-1) Y2(-7.5,-1.5) Y3(-7,-1.5) Y9(-4,-1.5) Y10(-3.5,-1.5) Y12(-2.5,-1.5) Y13(-2,-1.5) Y15(-1,-1.5) Y18(0.5,-1.5) Y19(1,-1.5) Y21(2,-1.5) Y22(2.5,-1.5) Y23(3,-1.5) Y24(3.5,-1.5) Y26(4.5,-1.5) Y31(7,-1.5) Y32(7.5,-1.5)
  silkscreen extent -9.26,-8.55 8.55,9.13

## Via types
v1: diameter 15.75, hole 11.81, Top Layer to Bottom Layer, 282 vias

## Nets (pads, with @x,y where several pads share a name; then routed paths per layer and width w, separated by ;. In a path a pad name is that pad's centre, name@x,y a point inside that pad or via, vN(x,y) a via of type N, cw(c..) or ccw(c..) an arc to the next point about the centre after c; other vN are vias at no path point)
$1N11425: R3.1 U1.AA29 | length 51.6
  Top Layer w4.5: v1(3547.71,3735.48) 3565.15,3735.48 U1.AA29@3566.01,3734.62
  Bottom Layer w6: v1(3547.71,3735.48) 3560.29,3735.48 3567,3728.77 3567,3719.28 R3.1@3568,3718.28
$1N11433: R4.1 UD1.A5 | length 53.9
  Top Layer w4.5: UD1.A5@4370.28,3807.2 4370.28,3808.05 v1(4382,3819.77)
  Bottom Layer w4.5: R4.1@4360,3840.61 4371.16,3840.61 4382,3829.77 v1(4382,3819.77)
$1N11434: R5.1 UD1.A8 | length 49.9
  Top Layer w4.5: UD1.A8@4464.76,3807.2 4464.76,3824.45 v1(4468.08,3827.77)
  Bottom Layer w4.5: v1(4468.08,3827.77) 4471.71,3824.14 R5.1@4471.71,3801.29
$1N11438: R1.1 UD1.G2 | length 133.9
  Top Layer w4.5: R1.1@4189,3700.61 4199.5,3700.61 4204,3696.11 4204,3663.77 4224.68,3643.09 4265.22,3643.09 UD1.G2@4275.79,3653.66
$1N11439: R2.1 UD1.T2 | length 119
  Top Layer w4.5: R2.1@4166,3423.93 4167.84,3425.77 4187,3425.77 4196,3434.77 4264.36,3434.77 UD1.T2@4275.79,3423.34
GND: C1.2 C2.2 C3.1 C4.1 C5.1 C6.1 C7.1 C8.1 C9.1 C10.1 C11.1 C12.1 C13.1 C14.1 C15.1 C16.1 C17.2 C18.1 C19.2 C20.1 C21.1 C22.1 C23.1 C24.1 C25.1 C26.1 C27.2 C28.2 C29.1 C30.1 C31.1 C32.2 C33.1 C34.1 C35.1 C36.1 C37.1 C38.1 C39.1 C40.1 C41.1 C42.1 C43.1 C44.1 C45.1 C46.2 C47.1 U1.A1 U1.AA15 U1.AA16 U1.AA18 U1.AA21 U1.AA22 U1.AA26 U1.AA30 U1.AA32 U1.AB10 U1.AB11 U1.AB12 U1.AB14 U1.AB15 U1.AB17 U1.AC1 U1.AC26 U1.AC29 U1.AC33 U1.AD9 U1.AD11 U1.AD13 U1.AD14 U1.AD20 U1.AD21 U1.AD22 U1.AE9 U1.AE12 U1.AE14 U1.AE18 U1.AE19 U1.AE20 U1.AE21 U1.AE22 U1.AE23 U1.AE24 U1.AE25 U1.AE26 U1.AE29 U1.AE32 U1.AG3 U1.AG6 U1.AG7 U1.AG11 U1.AG25 U1.AG28 U1.AG31 U1.AG33 U1.AH7 U1.AH9 U1.AH27 U1.AH32 U1.AJ13 U1.AJ19 U1.AJ21 U1.AJ23 U1.AK5 U1.AK11 U1.AK32 U1.AL3 U1.AL9 U1.AL12 U1.AL13 U1.AL14 U1.AM5 U1.AM20 U1.AM26 U1.AM29 U1.AN1 U1.AN10 U1.AN11 U1.AN18 U1.AN22 U1.AN24 U1.AN28 U1.AN31 U1.AN33 U1.C6 U1.C8 U1.C10 U1.C12 U1.C14 U1.C18 U1.C20 U1.D6 U1.E3 U1.F6 U1.F8 U1.F10 U1.F12 U1.G3 U1.G8 U1.G10 U1.G14 U1.G18 U1.G29 U1.J3 U1.J6 U1.J9 U1.J10 U1.J12 U1.J13 U1.J28 U1.J31 U1.K9 U1.K10 U1.K11 U1.K12 U1.K26 U1.L3 U1.L6 U1.L10 U1.L12 U1.L13 U1.L27 U1.L30 U1.L33 U1.M13 U1.N3 U1.N6 U1.N10 U1.N12 U1.N15 U1.N18 U1.N19 U1.N22 U1.N26 U1.N27 U1.N30 U1.P11 U1.P16 U1.P19 U1.P24 U1.R3 U1.R7 U1.R11 U1.R13 U1.R19 U1.R24 U1.R27 U1.T15 U1.T16 U1.T18 U1.T24 U1.U7 U1.U14 U1.U16 U1.U25 U1.U27 U1.V18 U1.V19 U1.W12 U1.W13 U1.W15 U1.W16 U1.W22 U1.W27 U1.W30 U1.Y15 U1.Y18 U1.Y22 U1.Y23 U1.Y26 UD1.A3 UD1.A10 UD1.AB3 UD1.AB5 UD1.AB8 UD1.AB10 UD1.C1 UD1.C5 UD1.C8 UD1.C12 UD1.D2 UD1.D4 UD1.D9 UD1.D11 UD1.E1 UD1.E5 UD1.E8 UD1.E12 UD1.G1 UD1.G3 UD1.G5 UD1.G8 UD1.G10 UD1.G12 UD1.J1 UD1.J3 UD1.J10 UD1.J12 UD1.K2 UD1.K4 UD1.K9 UD1.K11 UD1.N2 UD1.N4 UD1.N9 UD1.N11 UD1.P1 UD1.P3 UD1.P10 UD1.P12 UD1.T1 UD1.T3 UD1.T5 UD1.T8 UD1.T10 UD1.T12 UD1.V1 UD1.V5 UD1.V8 UD1.V12 UD1.W2 UD1.W4 UD1.W9 UD1.W11 UD1.Y1 UD1.Y5 UD1.Y8 UD1.Y12 | length 7606
  Top Layer w3: v1(3531.04,3883.65) 3530.43,3883.65 3530.04,3883.26 3531.04,3882.26 3531.81,3881.49 v1@3534.07,3879.23 ; 3538,3877.28 3538,3842.77 3556.19,3824.58 3556.19,3808.88 3566.01,3799.06 U1.AA32@3566.01,3793.68 ; U1.AE32@3644.75,3793.68 3644.75,3797.87 3654.62,3807.74 3654.62,3819.39 3657.94,3822.71 ; U1.AG31@3684.12,3773.99 3674.3,3783.81 3674.3,3798.09 3684.12,3807.91 ; U1.AG33@3684.12,3813.36 3687.42,3813.36 3693.83,3819.77 3693.99,3819.77 3703.99,3829.77 3736,3829.77 3762,3855.77 v1(3762,3857.77) ; U1.AK32@3743.18,3793.68 3753.04,3803.54 3753.04,3817.81 3760,3824.77 ; U1.AM20@3782.55,3557.46 3792.38,3547.63 3816.55,3547.63 ; U1.AM26@3782.55,3675.57 3792.41,3685.43 3818.91,3685.43 ; U1.AM29@3782.55,3734.62 3792.38,3744.44 3806.18,3744.44 3806.3,3744.49 3809.31,3747.5 3820.14,3747.5 ; v1(3827.75,3719.27) 3829.5,3719.27 3830,3718.77 3872,3718.77 3875,3721.77 3977,3721.77 4079,3619.77 4079,3610.77 4129.5,3560.37 4129.5,3560.27 4179.3,3510.47 4328.42,3510.47 ; v1(3851,3747.77) 3856,3752.77 3988,3752.77 4109,3631.77 4109,3619.77 4191.83,3536.94 4463.13,3536.94 4463.63,3536.44 4475.75,3536.44 v1(4482.01,3530.18) ; v1(4447,3487.77) 4424.3,3510.47 4349.14,3510.47 ; 4328.42,3510.47 4338.78,3500.11 4349.14,3510.47 ; 4328.42,3510.47 4349.14,3510.47
  Top Layer w4: 3657.94,3822.71 3658.42,3822.71 3674.98,3839.27 3681.35,3839.27 3698.48,3856.4 v1(3698.48,3858.23) ; 3684.12,3807.91 U1.AG33@3684.12,3813.36 ; v1(3823,3630.77) 3827,3630.77 3842.89,3646.66 3880.2,3646.66 3883.73,3650.2 3885.15,3650.2 ; v1(3868.94,3515.52) 3869.19,3515.77 3937,3515.77 3941,3511.77 v1(4002,3511.77)
  Top Layer w4.5: U1.AN22@3802.22,3596.75 3832.06,3596.83 3856,3620.77 3890,3620.77 3906,3604.77 v1(3906,3603.77)
  Top Layer w5: v1(3531.04,3883.65) 3531.04,3882.26 3531.04,3881.49 3531.81,3881.49 3533.79,3881.49 3538,3877.28 ; 3818.91,3685.43 3819.51,3686.03 3849.26,3686.03 v1(3855,3691.77) ; 3820.14,3747.5 3848.1,3747.5 3848.36,3747.76 v1(3851,3747.77) ; 3829.71,3783.77 3998,3783.77 4139,3642.77 4139,3633.77 4208,3564.77 4263.67,3564.77 UD1.K2@4275.79,3576.89 ; v1(3953,3557.02) 3974.26,3557.02 3979.01,3561.77 3997,3561.77 4010,3548.77 4010,3518.77 4003,3511.77 v1(4002,3511.77) ; v1(4323,3440.59) 4326.82,3436.77 4356.85,3436.77 ; v1(4479.67,3408.42) 4481.41,3410.16 4511.82,3410.16 v1(4513.2,3408.78) ; UD1.N9@4496.26,3500.11 4496.26,3515.93 ; v1(4544,3436.77) 4544.32,3436.45 v1@4570.38,3436.45 ; v1@4551.13,3641.25 v1@4574.68,3641.25
  Top Layer w6: U1.W30@3526.62,3754.23 3545.45,3754.23 v1(3547.71,3756.49) ; 3760,3824.77 3774.52,3824.77 3805.48,3855.73 3805.48,3856.95 v1(3805.76,3857.23) ; 3816.55,3547.63 3821.25,3547.63 3829,3555.38 v1(3829,3556.52) 3831.25,3558.77 3857,3558.77 3868,3547.77 3943.75,3547.77 v1(3953,3557.02) ; 3885.15,3650.2 3938.57,3650.2 3974,3614.77 v1(3974,3603.77) 3960,3589.77 3919,3589.77 3906,3602.77 v1(3906,3603.77) ; UD1.K2@4275.79,3576.89 4288.24,3564.44 4321.67,3564.44 4325,3567.77 4328.33,3564.44 4346.67,3564.44 v1(4353,3570.77) 4359.33,3564.44 4395.67,3564.44 4415,3583.77 v1(4426,3583.77) ; v1(4482.01,3530.18) 4496.26,3515.93
  Top Layer w8: 3667.8,3728.77 3681.63,3714.94 U1.AG28@3684.11,3714.86 ; U1.AN31@3802.23,3773.99 3803.23,3774.99 3813.21,3774.99 3821.99,3783.77 3829.71,3783.77 ; v1(4159.42,3475.02) 4168.67,3465.77 4235.54,3465.77 UD1.P1@4244.29,3474.52 ; v1(4205,3602.52) 4205.25,3602.77 4207,3602.77 4211.48,3607.25 4238.24,3607.25 4243.01,3602.48 UD1.J1@4244.29,3602.48 ; v1(4420,3632.77) 4440.89,3653.66 UD1.G8@4464.76,3653.66 ; v1(4421,3766.77) 4429,3758.77 4462.01,3758.77 UD1.C8@4464.76,3756.02 ; UD1.D9@4496.26,3730.43 4504.66,3730.43 4518,3743.77 4546,3743.77 v1(4547,3742.77)
  Top Layer w10: U1.W27@3526.62,3695.18 3524,3692.55 3524,3685.77 3534.27,3675.5 U1.Y26@3546.31,3675.5 U1.AA26@3566,3675.5 U1.AC26@3605.36,3675.49 ; v1(3547.71,3756.49) 3563.83,3756.49 U1.AA30@3566.01,3754.31 ; U1.AC29@3605.38,3734.62 3615.15,3734.62 v1(3626,3723.77) 3636.85,3734.62 U1.AE29@3644.75,3734.62 ; U1.AC33@3605.38,3813.36 3620,3827.98 3620,3855.77 v1(3616,3859.77) ; v1(3664,3753.77) 3644.78,3734.59 3650.6,3728.77 3667.8,3728.77 ; v1(3664,3753.77) U1.AG31@3684.11,3773.92 ; v1(3678,3674.52) 3678,3676.77 3696.48,3695.25 ; U1.AG28@3684.11,3714.86 3684.11,3707.62 3696.48,3695.25 ; U1.AG33@3684.12,3813.36 U1.AH32@3703.8,3793.68 ; v1(3698.48,3858.23) 3698.48,3865.25 3709,3875.77 3751,3875.77 3762,3864.77 v1(3762,3857.77) ; U1.AH27@3703.79,3695.18 3696.48,3695.25 ; v1(3720.96,3635.66) 3723.49,3633.13 U1.AJ23@3723.48,3616.43 3723.49,3598.82 v1(3720.95,3596.28) 3720.95,3579.68 U1.AJ21@3723.48,3577.06 3723.5,3557.84 v1(3721.16,3555.5) 3721.16,3540.1 U1.AJ19@3723.49,3537.77 ; U1.AN24@3802.23,3636.2 3803.08,3635.35 3818.42,3635.35 v1(3823,3630.77) ; U1.AN28@3802.22,3714.87 3821.95,3714.94 3823.59,3716.58 3823.81,3716.58 3826.5,3719.27 v1(3827.75,3719.27) ; U1.AN33@3802.23,3813.36 3802.23,3813.9 3802.63,3814.29 3802.63,3820.4 3831.31,3849.08 3831.31,3856.23 v1(3832.31,3857.23) ; v1(4211,3743.1) 4211,3743.76 4223.26,3756.02 4244.29,3756.02 4259.28,3741.03 v1(4259.63,3741.03) 4259.89,3740.77 4259.89,3740.43 4269.89,3730.43 UD1.D2@4275.79,3730.43 ; v1(4219,3667.77) 4233.11,3653.66 UD1.G1@4244.29,3653.66 ; v1(4220.92,3415.69) 4228.57,3423.34 UD1.T1@4244.29,3423.34 ; v1(4224,3373.25) 4224.52,3373.25 4224.84,3372.93 4229,3372.93 4229.77,3372.16 UD1.V1@4244.29,3372.16 ; v1(4226.74,3329.41) 4235.17,3320.98 4248.29,3320.98 4258.08,3330.77 v1(4261.08,3330.77) 4261.08,3331.86 UD1.W2@4275.79,3346.57 ; v1(4229.7,3699.04) 4235.5,3704.84 UD1.E1@4244.29,3704.84 ; v1(4262,3584.77) 4265.36,3581.41 4271.27,3581.41 UD1.K2@4275.79,3576.89 ; v1(4265,3492.77) 4272.34,3500.11 UD1.N2@4275.79,3500.11 ; v1(4298,3245.77) 4307.28,3255.05 UD1.AB3@4307.28,3269.8 ; UD1.J3@4307.28,3602.48 4309.29,3602.48 v1(4323,3588.77) ; UD1.G3@4307.28,3653.66 4310.12,3653.66 4322,3641.78 v1(4322,3640.77) ; UD1.A3@4307.28,3807.21 4312,3811.93 4312,3823.38 v1(4313.64,3825.02) ; UD1.P3@4307.33,3474.52 4324.08,3457.77 4324.08,3441.67 v1(4323,3440.59) 4322.89,3440.48 4322.89,3438.95 4307.28,3423.34 4323.25,3407.37 4323.25,3388.02 v1(4323,3387.77) 4323.96,3386.81 4323.96,3361.39 UD1.W4@4338.78,3346.57 ; v1(4322.13,3486.88) 4325.55,3486.88 UD1.N4@4338.78,3500.11 ; v1(4324,3766.77) 4324,3745.21 UD1.D4@4338.78,3730.43 ; UD1.K4@4338.78,3576.89 4344.9,3570.77 v1(4353,3570.77) ; 4356.85,3436.77 4370.28,3423.34 4376.74,3429.8 v1(4383.82,3429.8) ; UD1.AB5@4370.28,3269.8 4375.31,3264.77 v1(4435,3264.77) ; UD1.Y5@4370.28,3320.98 4394,3297.26 v1(4394,3296.77) ; UD1.V5@4370.28,3372.16 4370.28,3375.77 4380.28,3385.77 4390.75,3385.77 4401,3396.02 v1(4401,3396.77) ; UD1.G5@4370.28,3653.66 4387.19,3653.66 v1(4392.08,3648.77) ; UD1.E5@4370.28,3704.84 4384.35,3690.77 4395,3690.77 4414,3671.77 v1(4417,3671.77) ; UD1.C5@4370.28,3756.02 4381.03,3766.77 v1(4388,3766.77) ; v1(4443,3705.77) 4443.93,3704.84 UD1.E8@4464.75,3704.84 ; v1(4445.52,3373.91) 4446.86,3373.91 4447,3373.77 4449,3373.77 4450.61,3372.16 UD1.V8@4464.75,3372.16 ; UD1.AB8@4464.75,3269.8 4464.75,3255.02 4467,3252.77 v1(4470,3252.77) ; UD1.Y8@4464.76,3320.98 4468.25,3320.98 v1(4480,3332.73) 4493.84,3346.57 UD1.W9@4496.26,3346.57 ; UD1.T8@4464.75,3423.34 v1(4479.67,3408.42) ; UD1.N9@4496.26,3500.11 4496.26,3496.51 4518.25,3474.52 4527.76,3474.52 4527.76,3470.01 4544,3453.77 v1(4544,3436.77) 4543.68,3436.45 4540.87,3436.45 v1(4513.2,3408.78) v1@4511.17,3406.75 ; UD1.K9@4496.25,3576.89 4507.13,3587.77 4513.05,3587.77 v1(4514.01,3588.73) UD1.J10@4527.76,3602.48 ; v1(4515,3664.77) 4526.11,3653.66 4527.76,3653.66 4538.7,3642.72 v1(4543.94,3642.72) 4545.41,3641.25 v1@4551.13,3641.25 ; v1(4518,3251.77) 4518,3260.04 UD1.AB10@4527.76,3269.8 ; UD1.A10@4527.76,3807.2 4529.68,3807.2 v1(4542.35,3794.53) ; UD1.W11@4559.25,3346.57 4562.68,3346.57 v1(4574.62,3334.63) 4577.1,3334.63 UD1.Y12@4590.75,3320.98 ; UD1.K11@4559.25,3576.89 4565.2,3576.89 4574.08,3585.77 4575.64,3585.77 4575.97,3586.1 v1(4576.24,3586.1) ; UD1.D11@4559.24,3730.43 4573.58,3744.77 v1(4576,3744.77) 4577.68,3746.45 4581.18,3746.45 4603.52,3768.79 v1(4607.15,3768.79) ; v1@4570.38,3436.45 v1@4577.64,3436.45 ; v1(4574.65,3642.98) v1@4576.41,3642.98 ; v1@4574.68,3641.25 v1@4576.41,3642.98 ; v1(4577.71,3436.52) 4577.71,3436.38 4590.75,3423.34 4590.75,3424.52 4603,3436.77 v1(4616,3436.77) 4616,3439.77 4609.25,3446.52 4609.25,3456.01 4578.51,3486.75 v1(4572.6,3486.75) 4559.24,3500.11 4574.08,3514.95 v1(4574.08,3517.77) 4576.08,3519.77 v1(4576.08,3554.77) 4576.08,3585.94 v1(4576.24,3586.1) ; UD1.V12@4590.75,3372.16 4606.39,3372.16 v1(4617.05,3361.5) ; UD1.J12@4590.75,3602.44 4576.24,3587.93 v1(4576.24,3586.1) ; UD1.E12@4590.75,3704.84 4609.15,3704.84 v1(4614.08,3709.77) 4622.5,3709.77 C24.1@4637,3695.27 C33.1@4637,3722.27 ; C36.1@4637,3648.27 4612.27,3648.27 v1(4609.39,3651.15) 4606.88,3653.66 4587.09,3653.66 v1@4576.41,3642.98 ; C31.1@4637,3793.27 C30.1@4637,3815.27
  Inner1 w3: 4503,3731.77 4506.98,3731.77 4507.96,3730.79 4518.32,3730.79 4519.3,3731.77 4521,3731.77 ; 4535,3399.77 4537,3401.77 4549,3401.77 4551,3399.77
  Bottom Layer w8: C15.1@4318.5,3507.77 4318.5,3490.51 v1(4322.13,3486.88) ; C16.1@4563.5,3504.77 4563.5,3507.19 v1(4574.08,3517.77)
  Bottom Layer w10: v1(3526,3694.77) 3524,3692.77 3524,3683.77 3532.5,3675.27 C10.1@3546,3675.27 ; C11.1@3585,3675.27 C9.1@3606,3675.27 3606,3705.77 3609,3708.77 3623.5,3708.77 C17.2@3625,3710.27 3626,3711.27 v1(3626,3723.77) ; C18.1@3836,3666.61 3837,3667.61 3866,3667.61 3866,3675.92 ; v1(3855,3691.77) 3866,3680.77 3866,3675.92 ; C46.2@3874,3669.77 3872.15,3669.77 3866,3675.92 ; C45.1@4199.84,3652.77 4204,3652.77 v1(4219,3667.77) 4236.5,3667.77 C23.1@4237.5,3666.77 ; C44.1@4205,3692.93 4223.59,3692.93 v1(4229.7,3699.04) 4240.43,3709.77 4268,3709.77 4283.5,3694.27 C43.1@4283.5,3689.77 ; v1(4224,3373.25) 4229.84,3367.41 C27.2@4229.84,3352.77 ; v1(4298,3245.77) 4309,3256.77 C1.2@4350.16,3256.77 ; C32.2@4310.98,3847.68 4309.98,3846.68 4309.98,3828.68 v1(4313.64,3825.02) ; C41.1@4316.5,3743.77 4316.5,3759.27 v1(4324,3766.77) ; v1(4323,3387.77) 4329.84,3394.61 C22.1@4329.84,3412.77 ; v1(4323,3588.77) 4336,3601.77 C25.1@4336,3603.93 ; v1(4383.82,3429.8) 4383.82,3433.76 C2.2@4401.12,3451.06 ; v1(4392.08,3648.77) 4396.08,3652.77 C29.1@4410.16,3652.77 ; C26.1@4401.5,3690.77 4417,3675.27 v1(4417,3671.77) ; C3.1@4465.16,3227.77 4465.16,3248.93 4469,3252.77 v1(4470,3252.77) ; v1(4479.67,3408.42) 4485.12,3402.97 C4.1@4485.12,3386.43 ; C13.1@4484.84,3737.77 4505,3737.77 4515,3747.77 4542,3747.77 v1(4547,3742.77) ; C12.1@4486,3572.61 4487.85,3572.61 4503.97,3588.73 v1(4514.01,3588.73) ; C21.1@4511.5,3645.77 4511.5,3661.27 v1(4515,3664.77) ; v1(4518,3251.77) 4523.5,3257.27 C42.1@4538,3257.27 ; 4560,3657.93 4560,3657.63 v1(4574.65,3642.98) ; C5.1@4595.1,3793.07 4595.1,3780.84 v1(4607.15,3768.79)
  other v1: 4616,3477.77
SAA0: U1.AJ33 UD1.H2 | length 650.8
  Top Layer w3: U1.AJ33@3723.49,3813.36 3733.31,3803.54 3733.31,3789.46 3745.81,3776.96 v1(3745.81,3774.77)
  Top Layer w4.5: v1(4143,3671.77) 4157,3657.77 4163.16,3657.77 4200.16,3620.77 4229,3620.77 4233.5,3616.27 4263.99,3616.27 UD1.H2@4275.79,3628.07
  Inner5 w4.5: v1(3745.81,3774.77) 3748.81,3777.77 3842,3777.77 3881,3738.77 4045,3738.77 4076,3707.77 4087.06,3707.77 4123.06,3671.77 v1(4143,3671.77)
SAA1: U1.AJ32 UD1.J2 | length 679.2
  Top Layer w3: U1.AJ32@3723.49,3793.68 3723.49,3789.28 3733.31,3779.46 3733.31,3762.46 v1(3742,3753.77)
  Top Layer w4.5: v1(4158,3642.77) 4158,3629.77 4200,3587.77 4214,3587.77 4222.64,3596.41 4234.58,3596.41 4240.22,3590.77 4249.44,3590.77 4261.15,3602.48 UD1.J2@4275.79,3602.48
  Inner5 w4.5: v1(3742,3753.77) 3743.55,3753.77 3756.54,3766.76 3813.27,3766.76 3845.51,3734.52 3869.75,3734.52 3881.5,3722.77 4040.49,3722.77 4069.99,3693.27 4081.05,3693.27 4125.5,3648.82 4151.59,3648.73 4157.55,3642.77 v1(4158,3642.77)
SAA2: U1.AG30 UD1.H9 | length 929.9
  Top Layer w4: v1(4482,3615.03) 4482.26,3615.03 4495.3,3628.07 UD1.H9@4496.26,3628.07
  Top Layer w4.5: U1.AG30@3684.12,3754.31 3684.12,3752.65 v1(3702,3734.77)
  Inner5 w3: v1(3702,3734.77) 3704,3734.77 3717,3747.77 3729,3747.77 3736,3740.77 3776,3740.77 3778.13,3742.9
  Inner5 w4.5: 3778.13,3742.9 3784.87,3742.9 3823,3704.77 3845,3704.77 3848.19,3707.96 3858.81,3707.96 3874,3692.77 4029.47,3692.77 4057.95,3664.28 ; 4057.97,3664.27 4069.03,3664.27 4113.02,3620.28 4139.07,3620.23 4147.53,3611.77 4170.49,3611.77 4190.99,3632.27 4304.5,3632.27 4311,3625.77 4365.5,3625.77 4370,3621.27 4370,3612.77 4385,3597.77 4405,3597.77 4425,3617.77 4479.26,3617.77 v1(4482,3615.03)
SAA3: U1.AG29 UD1.H10 | length 1040.7
  Top Layer w4.5: U1.AG29@3684.12,3734.62 3684.12,3732.65 3702,3714.77 v1(3702,3713.77) ; v1(4515.01,3615.3) UD1.H10@4527.76,3628.07
  Inner2 w3: v1(3702,3713.77) 3702,3710.77 3713,3699.77 3777,3699.77 3785,3707.77
  Inner2 w4.5: 3785,3707.77 3810,3732.77 3840,3732.77 3846.5,3726.27 4166.5,3726.27 4175,3717.77 4190,3717.77 4225,3682.77 4237,3682.77 4273,3646.77 4301,3646.77 4309,3654.77 4364,3654.77 4385,3633.77 4394,3633.77 4411,3616.77 4411,3571.77 4415,3567.77 4455,3567.77 4460,3572.77 4460,3617.77 4473,3630.77 4499.54,3630.77 v1(4515.01,3615.3)
SAA4: U1.AJ30 UD1.H11 | length 980.8
  Top Layer w4: v1(4544,3611.77) 4544,3612.83 UD1.H11@4559.24,3628.07
  Top Layer w4.5: v1(3723.49,3734.28) U1.AJ30@3723.49,3754.31
  Inner5 w3: v1(3723.49,3734.28) 3725,3732.77 3780.49,3732.77
  Inner5 w4.5: 3780.49,3732.77 3821.49,3691.77 3835,3691.77 3849,3677.77 4023.96,3677.77 4051.95,3649.77 4063.02,3649.77 4107.01,3605.78 4133.04,3605.75 4141.52,3597.27 4176.5,3597.27 4197,3617.77 4259,3617.77 4265,3611.77 4326,3611.77 4348,3589.77 4363,3589.77 4375,3577.77 4375,3572.77 4380,3567.77 4487,3567.77 4493,3573.77 4524,3573.77 4544,3593.77 v1(4544,3611.77)
SAA5: U1.AJ31 UD1.J11 | length 1163.2
  Top Layer w4.5: v1(3704,3754.77) 3704.27,3754.77 U1.AJ31@3723.49,3773.99 ; v1(4539,3562.77) 4545.01,3568.78 4545.01,3587.78 4559.25,3602.02 UD1.J11@4559.25,3602.48
  Inner5 w4.5: v1(3704,3754.77) 3701,3754.77 3688,3741.77 3688,3708.77 3708,3688.77 3768,3688.77 3778,3678.77 3778,3655.77 3831,3602.77 3840,3602.77 3855,3587.77 4015.34,3587.77 4031.85,3571.26 4056.85,3571.26 4118.84,3509.27 4194.5,3509.27 4226,3477.77 4262,3477.77 4278,3461.77 4278,3459.77 4290,3447.77 4308,3447.77 4315,3454.77 4336,3454.77 4344,3446.77 4364,3446.77 4375,3457.77 4443,3457.77 4519,3533.77 4519,3542.77 v1(4539,3562.77)
SAB0: U1.AJ25 UD1.R2 | length 912.6
  Top Layer w4.5: v1(3721.95,3674.14) U1.AJ25@3721.95,3657.42 ; v1(4260,3460.77) 4271.84,3448.93 UD1.R2@4275.79,3448.93 ; U1.AJ25@3721.95,3657.42 3723.5,3655.88 U1.AJ25@3721.95,3657.42
  Inner2 w3: v1(3721.95,3674.14) 3721.95,3678.72 3736,3692.77 3780,3692.77
  Inner2 w4.5: 3780,3692.77 3796,3692.77 3801,3697.77 3826,3697.77 3842,3713.77 3871.72,3713.77 3876.22,3709.27 3876.22,3703.9 3880.72,3699.4 3886.72,3699.4 3891.22,3703.9 3891.22,3709.27 3895.72,3713.77 3901.72,3713.77 3906.22,3709.27 3906.22,3703.9 3910.72,3699.4 3916.72,3699.4 3921.22,3703.9 3921.22,3709.27 3925.72,3713.77 3931.72,3713.77 3936.22,3709.27 3936.22,3703.9 3940.72,3699.4 3946.72,3699.4 3951.22,3703.9 3951.22,3709.27 3955.72,3713.77 3961.72,3713.77 3966.22,3709.27 3966.22,3703.9 3970.72,3699.4 3976.72,3699.4 3981.22,3703.9 3981.22,3709.27 3985.72,3713.77 4012.63,3713.77 4017.13,3709.27 4017.13,3690.27 4021.63,3685.77 4027.63,3685.77 4032.13,3690.27 4032.13,3709.27 4036.63,3713.77 4042.63,3713.77 4047.13,3709.27 4047.13,3690.27 4051.63,3685.77 4057.63,3685.77 4062.13,3690.27 4062.13,3709.27 4066.63,3713.77 4072.5,3713.77 4085,3701.27 4085,3677.28 4125.51,3636.77 4137.02,3636.77 4245,3528.79 4245,3475.77 v1(4260,3460.77)
SAB1: U1.AH25 UD1.P2 | length 888.2
  Top Layer w4.5: v1(3700.95,3674.14) 3700.95,3658.73 U1.AH25@3703.81,3655.88 ; v1(4185,3492.52) 4185.25,3492.77 4199,3492.77 4212.25,3479.52 4232.75,3479.52 4240,3486.77 4250,3486.77 4258,3478.77 4271.54,3478.77 UD1.P2@4275.79,3474.52
  Inner2 w4.5: v1(3700.95,3674.14) 3715.32,3659.77 3836,3659.77 3856,3639.77 3892.56,3639.77 3897.06,3644.27 3897.06,3657.72 3901.56,3662.22 3907.56,3662.22 3912.06,3657.72 3912.06,3644.27 3916.56,3639.77 3922.56,3639.77 3927.06,3644.27 3927.06,3657.72 3931.56,3662.22 3937.56,3662.22 3942.06,3657.72 3942.06,3644.27 3946.56,3639.77 3952.56,3639.77 3957.06,3644.27 3957.06,3657.72 3961.56,3662.22 3967.56,3662.22 3972.06,3657.72 3972.06,3644.27 3976.56,3639.77 4057,3639.77 4103.5,3593.27 4118.99,3593.27 4160.8,3551.46 4160.8,3544.57 4139,3522.77 4139,3515.77 4148,3506.77 4162.69,3506.77 4169,3513.08 4169,3527.84 4173.53,3532.37 4179.89,3532.37 4185,3527.26 v1(4185,3492.52)
SAB2: U1.AL25 UD1.R9 | length 915.9
  Top Layer w4: v1(4481.12,3433.79) UD1.R9@4496.25,3448.93
  Top Layer w4.5: U1.AL25@3762.87,3655.89 v1(3762.87,3674.05)
  Inner2 w4.5: v1(3762.87,3674.05) 3767.15,3669.77 3841,3669.77 3848.5,3662.27 3879.5,3662.27 3890,3672.77 3975,3672.77 3990,3657.77 4059.51,3657.77 4109.51,3607.77 4125,3607.77 4200,3532.77 4200,3477.28 4246.51,3430.77 4313,3430.77 4317,3426.77 4361,3426.77 4382,3447.77 4467.14,3447.77 v1(4481.12,3433.79)
SAB3: U1.AK25 UD1.R10 | length 997.5
  Top Layer w4.5: v1(3741.96,3674.14) 3741.96,3657.1 U1.AK25@3743.18,3655.88 ; v1(4418,3486.77) 4443,3461.77 4514.92,3461.77 UD1.R10@4527.76,3448.93
  Inner2 w3: v1(3741.96,3674.14) 3745.28,3674.14 3757.69,3686.55 3775.22,3686.55 3782,3679.77 3802,3679.77
  Inner2 w4.5: 3802,3679.77 3806,3683.77 3842,3683.77 3849,3676.77 3869,3676.77 3880,3687.77 3980,3687.77 3995,3672.77 4069,3672.77 4119.5,3622.27 4131.01,3622.27 4215,3538.28 4215,3484.79 4254.02,3445.77 4304,3445.77 4318,3459.77 4331,3459.77 4345,3445.77 4362,3445.77 4379,3462.77 4394,3462.77 v1(4418,3486.77)
SAB4: U1.AJ27 UD1.R11 | length 1024.2
  Top Layer w4: v1(4503,3537.77) 4503,3536.77 4511,3528.77 4511,3495.92 4520.15,3486.77 4538,3486.77 4547,3477.77 4547,3468.78 4559.25,3456.53 UD1.R11@4559.25,3448.93
  Top Layer w4.5: v1(3722,3712.77) 3723.49,3711.28 U1.AJ27@3723.48,3695.18
  Inner5 w3: v1(3722,3712.77) 3734.5,3725.27 3774.5,3725.27 3777,3722.77
  Inner5 w4.5: 3777,3722.77 3777,3721.77 3819,3679.77 3830,3679.77 3847,3662.77 4018.44,3662.77 4045.94,3635.27 4057.01,3635.27 4101,3591.28 4127.01,3591.27 4135.51,3582.77 4208,3582.77 4223.25,3598.02 4301.75,3598.02 4308,3591.77 4308,3580.77 4336,3552.77 4488,3552.77 v1(4503,3537.77)
SAB5: U1.AL29 UD1.P11 | length 1061.5
  Top Layer w4: v1(4554,3544.77) 4548,3538.77 4548,3488.77 4559.25,3477.52 UD1.P11@4559.25,3474.52
  Top Layer w4.5: U1.AL29@3762.86,3734.62 v1(3762.86,3753.51)
  Inner5 w4.5: v1(3762.86,3753.51) 3814.26,3753.51 3846.5,3721.27 3862.49,3721.27 3875.99,3707.77 4034.98,3707.77 4063.98,3678.77 4075.04,3678.77 4119.03,3634.78 4145.1,3634.71 4153.04,3626.77 4164,3626.77 4186,3648.77 4305,3648.77 4311.25,3655.02 4363.75,3655.02 4385,3633.77 4399,3633.77 4414,3648.77 4467,3648.77 4487,3628.77 4533,3628.77 4534,3627.77 4551,3627.77 4560,3618.77 4560,3550.77 v1(4554,3544.77)
SCKE0-A: U1.AM31 UD1.J4 | length 867.9
  Top Layer w3: U1.AM31@3782.55,3773.99 3788.32,3773.99 3798.19,3783.86 3809.1,3783.86 3821.45,3796.21
  Top Layer w4.5: 3821.45,3796.21 4002.56,3796.21 4088.39,3710.38 v1(4104.61,3710.38) ; UD1.J4@4338.78,3602.48 4338.78,3593.28 4343.29,3588.77 4384,3588.77 v1(4390,3582.77)
  Inner2 w4.5: v1(4104.61,3710.38) 4104.61,3689.69 4137.28,3657.02 4163.91,3657.02 4198.16,3622.77 4224,3622.77 4246,3600.77 4246,3556.77 4275,3527.77 4360,3527.77 4390,3557.77 v1(4390,3582.77)
SCKE0-B: U1.AN27 UD1.P4 | length 843.6
  Top Layer w3: 3839.47,3695.25 3848.99,3704.77 3883.08,3704.77
  Top Layer w3.8: U1.AN27@3802.22,3695.17 3839.47,3695.25
  Top Layer w4.5: 3883.08,3704.77 3888.08,3699.77 3971,3699.77 4060,3610.77 4060,3559.77 4077,3542.77 4100,3542.77 4151,3491.77 4158.5,3491.77 4165,3498.27 4165,3506.77 4132.99,3538.78 v1(4130.01,3538.78) ; UD1.P4@4338.78,3474.52 4342.75,3474.52 v1(4355,3486.77)
  Inner5 w4.5: v1(4130.01,3538.78) 4206.01,3538.78 4212.02,3532.77 4290,3532.77 4315,3507.77 4363,3507.77 4368,3502.77 4368,3493.27 4361.5,3486.77 v1(4355,3486.77)
SCKE1-A: U1.AL31 UD1.J5 | length 883.1
  Top Layer w3: U1.AL31@3762.86,3773.99 3772.73,3783.86 3786.63,3783.86 3792.41,3789.65 3792.42,3799.19 3796.73,3803.5 3806.32,3803.5 3822.07,3819.26
  Top Layer w4: UD1.J5@4370.28,3602.48 4370.79,3602.48 4371.08,3602.77 4379,3602.77 v1(4390,3613.77)
  Top Layer w4.5: 3822.08,3819.26 3824.75,3819.26 3825.26,3819.77 4012,3819.77 4095,3736.77 4119.51,3736.77 4133.5,3722.78 4133.5,3705.27 4145.57,3693.2 4161.43,3693.2 v1(4170,3701.77)
  Inner2 w4.5: v1(4170,3701.77) 4170,3701.27 4185.51,3701.27 4204.01,3682.76 4204,3660.77 4213,3651.77 4246,3651.77 4275,3622.77 4295,3622.77 4307,3610.77 4307,3575.77 4315,3567.77 4330,3567.77 4340,3577.77 4340,3617.77 4347,3624.77 4369,3624.77 4380,3613.77 v1(4390,3613.77)
SCKE1-B: U1.AM27 UD1.P5 | length 859.9
  Top Layer w3: U1.AM27@3782.55,3695.25 3792.42,3705.12 3810.65,3705.12 3814,3701.77 3836,3701.77 3846,3711.77 3876.4,3711.77
  Top Layer w4.5: 3876.4,3711.77 3877.4,3712.77 3972.99,3712.77 4070.59,3615.17 4070.59,3567.17 4081.99,3555.77 4100,3555.77 v1(4106.51,3562.28) ; UD1.P5@4370.28,3474.52 4371.75,3474.52 v1(4385,3487.77)
  Inner5 w4.5: v1(4106.51,3562.28) 4112.49,3562.28 4121,3553.77 4211.53,3553.77 4217.53,3547.77 4297,3547.77 4322,3522.77 4378.18,3522.77 4382.68,3518.27 4382.68,3507.27 4387.18,3502.77 4396.18,3502.77 4400.68,3507.27 4400.68,3518.27 4405.18,3522.77 4413,3522.77 4417,3518.77 4417,3506.77 4398,3487.77 v1(4385,3487.77)
SCKN-A: U1.AN30 UD1.J9 | length 850.5
  Top Layer w3: U1.AN30@3802.23,3754.31 3804.08,3756.16 3820.4,3756.16 3826.88,3762.64 3831.13,3762.64 3835.86,3757.91 3840.12,3757.91 3844.98,3762.77 ; 4485.51,3565.02 4485.51,3565.77 4484.51,3566.77 4484.51,3599.2 4487.79,3602.48 UD1.J9@4496.26,3602.48
  Top Layer w5: 3844.98,3762.77 3990.84,3762.77 4119,3634.61 4119,3622.77 4196.83,3544.94 4476.66,3544.94 4485.51,3553.79 4485.51,3565.02
SCKN-B: U1.AN29 UD1.P9 | length 833.7
  Top Layer w3: U1.AN29@3802.23,3734.62 3806.24,3734.62 3812.06,3740.44 3840.66,3740.43 3845.82,3735.27 3846.5,3735.27 3846.61,3735.16 3860.39,3735.16 3871,3745.77 3908.32,3745.77 3909.32,3744.77 3916.15,3744.77 ; 4458.14,3528.53 4458.52,3528.53 4459.52,3527.53 4461.87,3527.53 4462.87,3526.53 4465.56,3526.53 4486,3506.09 4486,3484.78 UD1.P9@4496.26,3474.52
  Top Layer w5: 3916.15,3744.77 3982.15,3744.77 4099,3627.92 4099,3617.92 4188.39,3528.53 4458.14,3528.53
SCKP-A: U1.AM30 UD1.J8 | length 848.8
  Top Layer w3: U1.AM30@3782.55,3754.31 3792.41,3764.16 3816.4,3764.16 3825.01,3772.77 3844.98,3772.77 ; UD1.J8@4464.76,3602.48 4476.51,3590.73 4476.51,3566.77 4475.51,3565.77 4475.51,3565.02
  Top Layer w5: 3844.98,3772.77 3994.99,3772.77 4129,3638.76 4129,3626.92 4200.98,3554.94 4472.51,3554.94 4475.51,3557.94 4475.51,3565.02
SCKP-B: U1.AM28 UD1.P8 | length 863.2
  Top Layer w3: U1.AM28@3782.55,3714.94 3792.38,3724.77 3809,3724.77 3816.66,3732.43 3837.34,3732.43 3842.5,3727.27 3843.18,3727.27 3843.29,3727.16 3863.71,3727.16 3874.32,3737.77 3878.56,3737.77 3881.56,3734.77 3881.56,3731.77 3884.56,3728.77 3890.56,3728.77 3893.56,3731.77 3893.56,3734.77 3896.56,3737.77 3905,3737.77 3908,3734.77 3916.15,3734.77 ; 4458.14,3518.53 4462.24,3518.53 4478,3502.77 4478,3477.53 4474.99,3474.52 UD1.P8@4464.76,3474.52
  Top Layer w5: 3916.15,3734.77 3978,3734.77 4089,3623.77 4089,3613.77 4184.24,3518.53 4458.14,3518.53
